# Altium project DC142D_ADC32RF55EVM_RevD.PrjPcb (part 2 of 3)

## Sheet DC142D_ADC32RF55_MUX_RevA1.SchDoc: MUXes
size 431 x 279 mm; Date: Not shown in title block; ApprovedBy: Not shown in title block; CheckedBy: Not shown in title block; Author: Not shown in title block; CompanyName: Not shown in title block; DrawnBy: CW; Engineer: Not shown in title block; Organization: Not shown in title block; Address1: Not shown in title block; Address2: Not shown in title block; Address3: Not shown in title block; Address4: Not shown in title block; DocumentNumber: 10; Revision: Use project parameter SCH_Rev; SheetNumber: 6; SheetTotal: 13; PageSetup: Record=PageOptions¦CenterHorizontal=True¦CenterVertical=True¦PrintScale=1.00¦XCorrection=1.00¦YCorrection=1.00¦PrintKind=0¦BorderSize=5000000¦LeftOffset=0¦BottomOffset=0¦Orientation=2¦PaperLength=1000¦PaperWidth=1000¦Scale=100¦PaperSource=15¦PrintQuality=600¦MediaType=1¦DitherType=10¦PaperKind=Letter¦PrintScaleMode=1
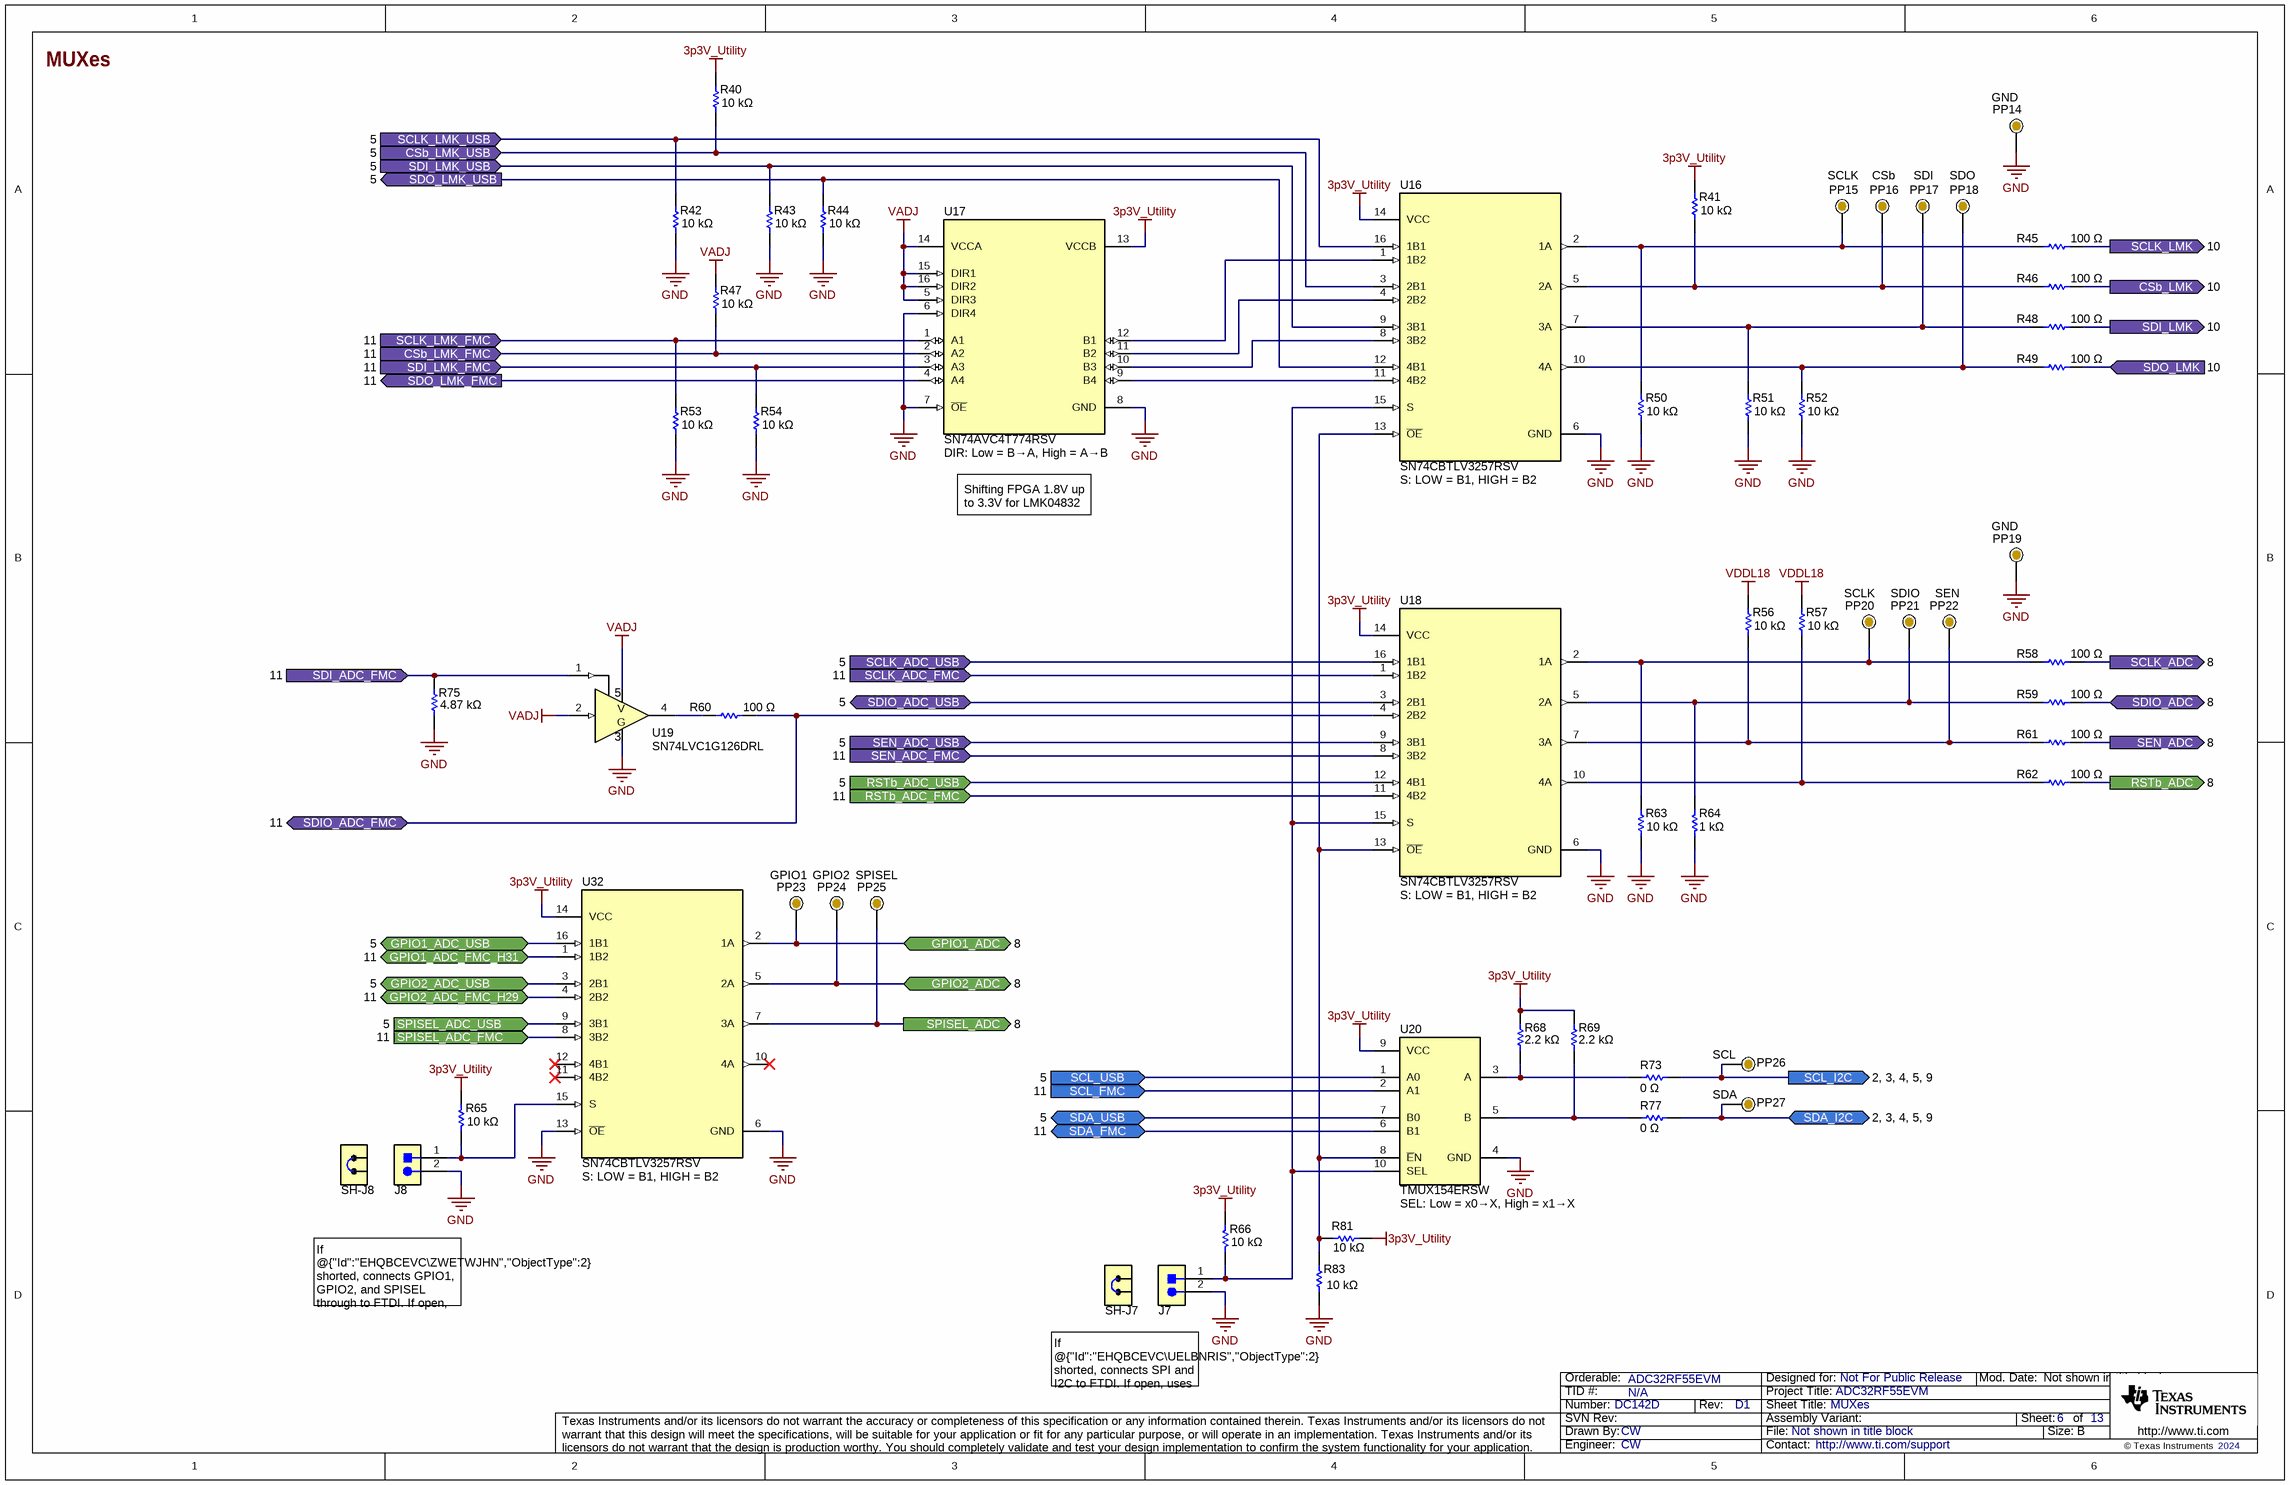
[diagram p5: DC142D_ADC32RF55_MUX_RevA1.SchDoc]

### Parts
J7  TSW-102-14-L-S  [PBC02SAAN]  (value not drawn)
J8  TSW-102-14-L-S  [PBC02SAAN]  (value not drawn)
PP14  Text1: GND  [ProbePoint_TH_40mil]  (hidden comment: Probe Point)  (no BOM)
PP15  Text1: SCLK  [ProbePoint_TH_40mil]  (hidden comment: Probe Point)  (no BOM)
PP16  Text1: CSb  [ProbePoint_TH_40mil]  (hidden comment: Probe Point)  (no BOM)
PP17  Text1: SDI  [ProbePoint_TH_40mil]  (hidden comment: Probe Point)  (no BOM)
PP18  Text1: SDO  [ProbePoint_TH_40mil]  (hidden comment: Probe Point)  (no BOM)
PP19  Text1: GND  [ProbePoint_TH_40mil]  (hidden comment: Probe Point)  (no BOM)
PP20  Text1: SCLK  [ProbePoint_TH_40mil]  (hidden comment: Probe Point)  (no BOM)
PP21  Text1: SDIO  [ProbePoint_TH_40mil]  (hidden comment: Probe Point)  (no BOM)
PP22  Text1: SEN  [ProbePoint_TH_40mil]  (hidden comment: Probe Point)  (no BOM)
PP23  Text1: GPIO1  [ProbePoint_TH_40mil]  (hidden comment: Probe Point)  (no BOM)
PP24  Text1: GPIO2  [ProbePoint_TH_40mil]  (hidden comment: Probe Point)  (no BOM)
PP25  Text1: SPISEL  [ProbePoint_TH_40mil]  (hidden comment: Probe Point)  (no BOM)
PP26  Text1: SCL  [ProbePoint_TH_40mil]  (hidden comment: Probe Point)  (no BOM)
PP27  Text1: SDA  [ProbePoint_TH_40mil]  (hidden comment: Probe Point)  (no BOM)
R40  value 10 kΩ  [0201]  (hidden comment: ERJ-1GNF1002C)
R41  value 10 kΩ  [0201]  (hidden comment: ERJ-1GNF1002C)
R42  value 10 kΩ  [0201]  (hidden comment: ERJ-1GNF1002C)
R43  value 10 kΩ  [0201]  (hidden comment: ERJ-1GNF1002C)
R44  value 10 kΩ  [0201]  (hidden comment: ERJ-1GNF1002C)
R45  value 100 Ω  [0201]  (hidden comment: ERJ-1GNF1000C)
R46  value 100 Ω  [0201]  (hidden comment: ERJ-1GNF1000C)
R47  value 10 kΩ  [0201]  (hidden comment: ERJ-1GNF1002C)
R48  value 100 Ω  [0201]  (hidden comment: ERJ-1GNF1000C)
R49  value 100 Ω  [0201]  (hidden comment: ERJ-1GNF1000C)
R50  value 10 kΩ  [0201]  (hidden comment: ERJ-1GNF1002C)
R51  value 10 kΩ  [0201]  (hidden comment: ERJ-1GNF1002C)
R52  value 10 kΩ  [0201]  (hidden comment: ERJ-1GNF1002C)
R53  value 10 kΩ  [0201]  (hidden comment: ERJ-1GNF1002C)
R54  value 10 kΩ  [0201]  (hidden comment: ERJ-1GNF1002C)
R56  value 10 kΩ  [0201]  (hidden comment: ERJ-1GNF1002C)
R57  value 10 kΩ  [0201]  (hidden comment: ERJ-1GNF1002C)
R58  value 100 Ω  [0201]  (hidden comment: ERJ-1GNF1000C)
R59  value 100 Ω  [0201]  (hidden comment: ERJ-1GNF1000C)
R60  value 100 Ω  [0201]  (hidden comment: ERJ-1GNF1000C)
R61  value 100 Ω  [0201]  (hidden comment: ERJ-1GNF1000C)
R62  value 100 Ω  [0201]  (hidden comment: ERJ-1GNF1000C)
R63  value 10 kΩ  [0201]  (hidden comment: ERJ-1GNF1002C)
R64  value 1 kΩ  [0201]  (hidden comment: ERJ-1GNF1001C)
R65  value 10 kΩ  [0201]  (hidden comment: ERJ-1GNF1002C)
R66  value 10 kΩ  [0201]  (hidden comment: ERJ-1GNF1002C)
R68  value 2.2 kΩ  [0201]  (hidden comment: ERJ-1GNF2201C)
R69  value 2.2 kΩ  [0201]  (hidden comment: ERJ-1GNF2201C)
R73  value 0 Ω  [0201]  (hidden comment: ERJ-1GN0R00C)
R75  value 4.87 kΩ  [0402L]  (hidden comment: ERJ-2RKF4871X)
R77  value 0 Ω  [0201]  (hidden comment: ERJ-1GN0R00C)
R81  value 10 kΩ  [0201]  (hidden comment: ERJ-1GNF1002C)
R83  value 10 kΩ  [0201]  (hidden comment: ERJ-1GNF1002C)
SH-J7  SPC02SYAN  [SPC02SYAN]  (value not drawn)
SH-J8  SPC02SYAN  [SPC02SYAN]  (value not drawn)
U16  SN74CBTLV3257RSV  Text1: S: LOW = B1, HIGH = B2  [RSV0016A]
U17  SN74AVC4T774RSV  Text1: DIR: Low = B→A, High = A→B  [RSV0016A]
U18  SN74CBTLV3257RSV  Text1: S: LOW = B1, HIGH = B2  [RSV0016A]
U19  SN74LVC1G126DRL  [DRL0005A]
U20  TMUX154ERSW  Text1: SEL: Low = x0→X, High = x1→X  [RSW0010A]
U32  SN74CBTLV3257RSV  Text1: S: LOW = B1, HIGH = B2  [RSV0016A]

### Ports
CSb_LMK (out, see 10), CSb_LMK_FMC (in, see 11), CSb_LMK_USB (in, see 5), GPIO1_ADC (bidir, see 8), GPIO1_ADC_FMC_H31 (bidir, see 11), GPIO1_ADC_USB (bidir, see 5), GPIO2_ADC (bidir, see 8), GPIO2_ADC_FMC_H29 (bidir, see 11), GPIO2_ADC_USB (bidir, see 5), RSTb_ADC (out, see 8), RSTb_ADC_FMC (in, see 11), RSTb_ADC_USB (in, see 5), SCL_FMC (in, see 11), SCL_I2C (out, see 2, 3, 4, 5, 9), SCL_USB (in, see 5), SCLK_ADC (out, see 8), SCLK_ADC_FMC (in, see 11), SCLK_ADC_USB (in, see 5), SCLK_LMK (out, see 10), SCLK_LMK_FMC (in, see 11), SCLK_LMK_USB (in, see 5), SDA_FMC (bidir, see 11), SDA_I2C (bidir, see 2, 3, 4, 5, 9), SDA_USB (bidir, see 5), SDI_ADC_FMC (in, see 11), SDI_LMK (out, see 10), SDI_LMK_FMC (in, see 11), SDI_LMK_USB (in, see 5), SDIO_ADC (bidir, see 8), SDIO_ADC_FMC (bidir, see 11), SDIO_ADC_USB (bidir, see 5), SDO_LMK (in, see 10), SDO_LMK_FMC (out, see 11), SDO_LMK_USB (out, see 5), SEN_ADC (out, see 8), SEN_ADC_FMC (in, see 11), SEN_ADC_USB (in, see 5), SPISEL_ADC (out, see 8), SPISEL_ADC_FMC (in, see 11), SPISEL_ADC_USB (in, see 5)

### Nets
3p3V_Utility: R40.1 R41.1 R65.2 R66.2 R68.2 R69.2 R81.1 U16.14(VCC) U17.13(VCCB) U18.14(VCC) U20.9(VCC) U32.14(VCC)
GND: J7.2 J8.2 PP14.1 PP19.1 R42.2 R43.2 R44.2 R50.2 R51.2 R52.2 R53.2 R54.2 R63.2 R64.2 R75.2 R83.1 U16.6(GND) U17.6(DIR4) U17.7(~{OE}) U17.8(GND) U18.6(GND) U19.3(GND) U20.4(GND) U32.6(GND) U32.13(~{OE})
VADJ: R47.1 U17.5(DIR3) U17.14(VCCA) U17.15(DIR1) U17.16(DIR2) U19.2(A) U19.5(VCC)
VDDL18: R56.1 R57.1
CSb_LMK: R46.2 ; port CSb_LMK
CSb_LMK_FMC: R47.2 U17.2(A2) ; port CSb_LMK_FMC
CSb_LMK_USB: R40.2 U16.3(2B1) ; port CSb_LMK_USB
GPIO1_ADC: PP23.1 U32.2(1A) ; port GPIO1_ADC
GPIO1_ADC_FMC_H31: U32.1(1B2) ; port GPIO1_ADC_FMC_H31
GPIO1_ADC_USB: U32.16(1B1) ; port GPIO1_ADC_USB
GPIO2_ADC: PP24.1 U32.5(2A) ; port GPIO2_ADC
GPIO2_ADC_FMC_H29: U32.4(2B2) ; port GPIO2_ADC_FMC_H29
GPIO2_ADC_USB: U32.3(2B1) ; port GPIO2_ADC_USB
RSTb_ADC: R62.2 ; port RSTb_ADC
RSTb_ADC_FMC: U18.11(4B2) ; port RSTb_ADC_FMC
RSTb_ADC_USB: U18.12(4B1) ; port RSTb_ADC_USB
SCL_FMC: U20.2(A1) ; port SCL_FMC
SCL_I2C: PP26.1 R73.2 ; port SCL_I2C
SCL_USB: U20.1(A0) ; port SCL_USB
SCLK_ADC: R58.2 ; port SCLK_ADC
SCLK_ADC_FMC: U18.1(1B2) ; port SCLK_ADC_FMC
SCLK_ADC_USB: U18.16(1B1) ; port SCLK_ADC_USB
SCLK_LMK: R45.2 ; port SCLK_LMK
SCLK_LMK_FMC: R53.1 U17.1(A1) ; port SCLK_LMK_FMC
SCLK_LMK_USB: R42.1 U16.16(1B1) ; port SCLK_LMK_USB
SDA_FMC: U20.6(B1) ; port SDA_FMC
SDA_I2C: PP27.1 R77.2 ; port SDA_I2C
SDA_USB: U20.7(B0) ; port SDA_USB
SDI_ADC_FMC: R75.1 U19.1(~{OE}) ; port SDI_ADC_FMC
SDI_LMK: R48.2 ; port SDI_LMK
SDI_LMK_FMC: R54.1 U17.3(A3) ; port SDI_LMK_FMC
SDI_LMK_USB: R43.1 U16.9(3B1) ; port SDI_LMK_USB
SDIO_ADC: R59.2 ; port SDIO_ADC
SDIO_ADC_FMC: R60.2 U18.4(2B2) ; port SDIO_ADC_FMC
SDIO_ADC_USB: U18.3(2B1) ; port SDIO_ADC_USB
SDO_LMK: R49.2 ; port SDO_LMK
SDO_LMK_FMC: U17.4(A4) ; port SDO_LMK_FMC
SDO_LMK_USB: R44.1 U16.12(4B1) ; port SDO_LMK_USB
SEN_ADC: R61.2 ; port SEN_ADC
SEN_ADC_FMC: U18.8(3B2) ; port SEN_ADC_FMC
SEN_ADC_USB: U18.9(3B1) ; port SEN_ADC_USB
SPISEL_ADC: PP25.1 U32.7(3A) ; port SPISEL_ADC
SPISEL_ADC_FMC: U32.8(3B2) ; port SPISEL_ADC_FMC
SPISEL_ADC_USB: U32.9(3B1) ; port SPISEL_ADC_USB
NetJ7_1: J7.1 R66.1 U16.15(S) U18.15(S) U20.10(SEL)
NetJ8_1: J8.1 R65.1 U32.15(S)
NetPP15_1: PP15.1 R45.1 R50.1 U16.2(1A)
NetPP16_1: PP16.1 R41.2 R46.1 U16.5(2A)
NetPP17_1: PP17.1 R48.1 R51.1 U16.7(3A)
NetPP18_1: PP18.1 R49.1 R52.1 U16.10(4A)
NetPP20_1: PP20.1 R58.1 R63.1 U18.2(1A)
NetPP21_1: PP21.1 R59.1 R64.1 U18.5(2A)
NetPP22_1: PP22.1 R56.2 R61.1 U18.7(3A)
NetR57_2: R57.2 R62.1 U18.10(4A)
NetR60_1: R60.1 U19.4(Y)
NetR68_1: R68.1 R73.1 U20.3(A)
NetR69_1: R69.1 R77.1 U20.5(B)
NetR81_2: R81.2 R83.2 U16.13(~{OE}) U18.13(~{OE}) U20.8(~{E}N)
NetU16_1: U16.1(1B2) U17.12(B1)
NetU16_4: U16.4(2B2) U17.11(B2)
NetU16_8: U16.8(3B2) U17.10(B3)
NetU16_11: U16.11(4B2) U17.9(B4)

Not connected (* = marked no-connect by the designer): U32 10(4A)* 11(4B2)* 12(4B1)*

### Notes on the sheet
- Shifting FPGA 1.8V up to 3.3V for LMK04832
- If @{"Id":"EHQBCEVC\ZWETWJHN","ObjectType":2} shorted, connects GPIO1, GPIO2, and SPISEL through to FTDI. If open, uses FPGA.
- If @{"Id":"EHQBCEVC\UELBNRIS","ObjectType":2} shorted, connects SPI and I2C to FTDI. If open, uses FPGA.

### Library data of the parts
J7 J8 = TSW-102-14-L-S: Header, 100mil, 2x1, Gold, TH; Manufacturer: Samtec; Alt Manufacturer: Sullins Connector Solutions; UniqueID: cmp00014; Pitch (mm): 2.54
PP14-PP27 = cmp00025: Probe Point that can be used in lue of a test point
R40-R44 R47 R50-R54 R56 R57 R63 R65 R66 R81 R83 = RSMD020100762: RES SMD 10K OHM 1% 1/20W 0201; Manufacturer: Panasonic Electronic Components; CompType: Resistor SMD; Power (Watts): 0.05W, 1/20W; Temperature Coefficient: ±200ppm/°C
R45 R46 R48 R49 R58-R62 = RSMD020100289: RES SMD 100 OHM 1% 1/20W 0201; Manufacturer: Panasonic Electronic Components; CompType: Resistor SMD; Power (Watts): 0.05W, 1/20W; Temperature Coefficient: ±200ppm/°C
R64 = RSMD020100143: RES SMD 1K OHM 1% 1/20W 0201; Manufacturer: Panasonic Electronic Components; CompType: Resistor SMD; Power (Watts): 0.05W, 1/20W; Temperature Coefficient: ±200ppm/°C
R68 R69 = RSMD020100606: RES SMD 2.2K OHM 1% 1/20W 0201; Manufacturer: Panasonic Electronic Components; CompType: Resistor SMD; Power (Watts): 0.05W, 1/20W; Temperature Coefficient: ±200ppm/°C
R73 R77 = RSMD020101699: RES SMD 0 OHM JUMPER 1/20W 0201; Manufacturer: Panasonic Electronic Components; CompType: Resistor SMD; Power (Watts): 0.05W, 1/20W
R75 = RSMD040202616: RES SMD 4.87K OHM 1% 1/10W 0402; Manufacturer: Panasonic Electronic Components; CompType: Resistor SMD; Power (Watts): 0.1W, 1/10W; Temperature Coefficient: ±100ppm/°C; SizeX_mm: 1; SizeY_mm: 0.5; SizeZ_mm: 0.4
SH-J7 SH-J8 = cmp00093: 2 (1 x 2) Position Shunt Connector Black Closed Top 0.100" (2.54mm) Gold; Manufacturer: Sullins; Value: 1x2; Note: You can "mate" this to a header by matching the designator.  i.e. use SH-J3 for header J3; Pitch (mm): 2.54
U16 U18 U32 = SN74CBTLV3257RSV: Low-Voltage 4-Bit 1-of-2 FET Multiplexer/Demultiplexe; PartNumber: SN74CBTLV3257RSVR; Manufacturer: Texas Instruments; UniqueID: cmp00269; CompType: MUX
U17 = cmp00171: Translation - Voltage Levels 4-bit dual-supply bus transceiver with 3-state outputs and independent direction control inputs; Manufacturer: Texas Instruments; Alt PartNumber: SN74AXC4T774RSV; CompType: Level Shifter
U19 = SN74LVC1G126DRL: Single Bus Buffer Gate With 3-State Outputs. Active high enable.; Manufacturer: Texas Instruments
U20 = cmp00300: ESD-Protected, Low Capacitance, 2-Channel, 2:1 Switch, With Powered-off Protection; PartNumber: TMUX154ERSWR; Manufacturer: Texas Instruments; CompType: MUX

## Sheet DC142D_ADC32RF55_ADC_Input_RevA1.SchDoc: ADC EVM RF Input
size 431 x 279 mm; Date: Not shown in title block; ApprovedBy: Not shown in title block; CheckedBy: Not shown in title block; Author: Not shown in title block; CompanyName: Not shown in title block; DrawnBy: CW; Engineer: Not shown in title block; Organization: Not shown in title block; Address1: Not shown in title block; Address2: Not shown in title block; Address3: Not shown in title block; Address4: Not shown in title block; DocumentNumber: 2; Revision: Use project parameter SCH_Rev; SheetNumber: 7; SheetTotal: 13; PageSetup: Record=PageOptions¦CenterHorizontal=True¦CenterVertical=True¦PrintScale=1.00¦XCorrection=1.00¦YCorrection=1.00¦PrintKind=0¦BorderSize=5000000¦LeftOffset=0¦BottomOffset=0¦Orientation=2¦PaperLength=1000¦PaperWidth=1000¦Scale=100¦PaperSource=15¦PrintQuality=600¦MediaType=1¦DitherType=10¦PaperKind=Letter¦PrintScaleMode=1
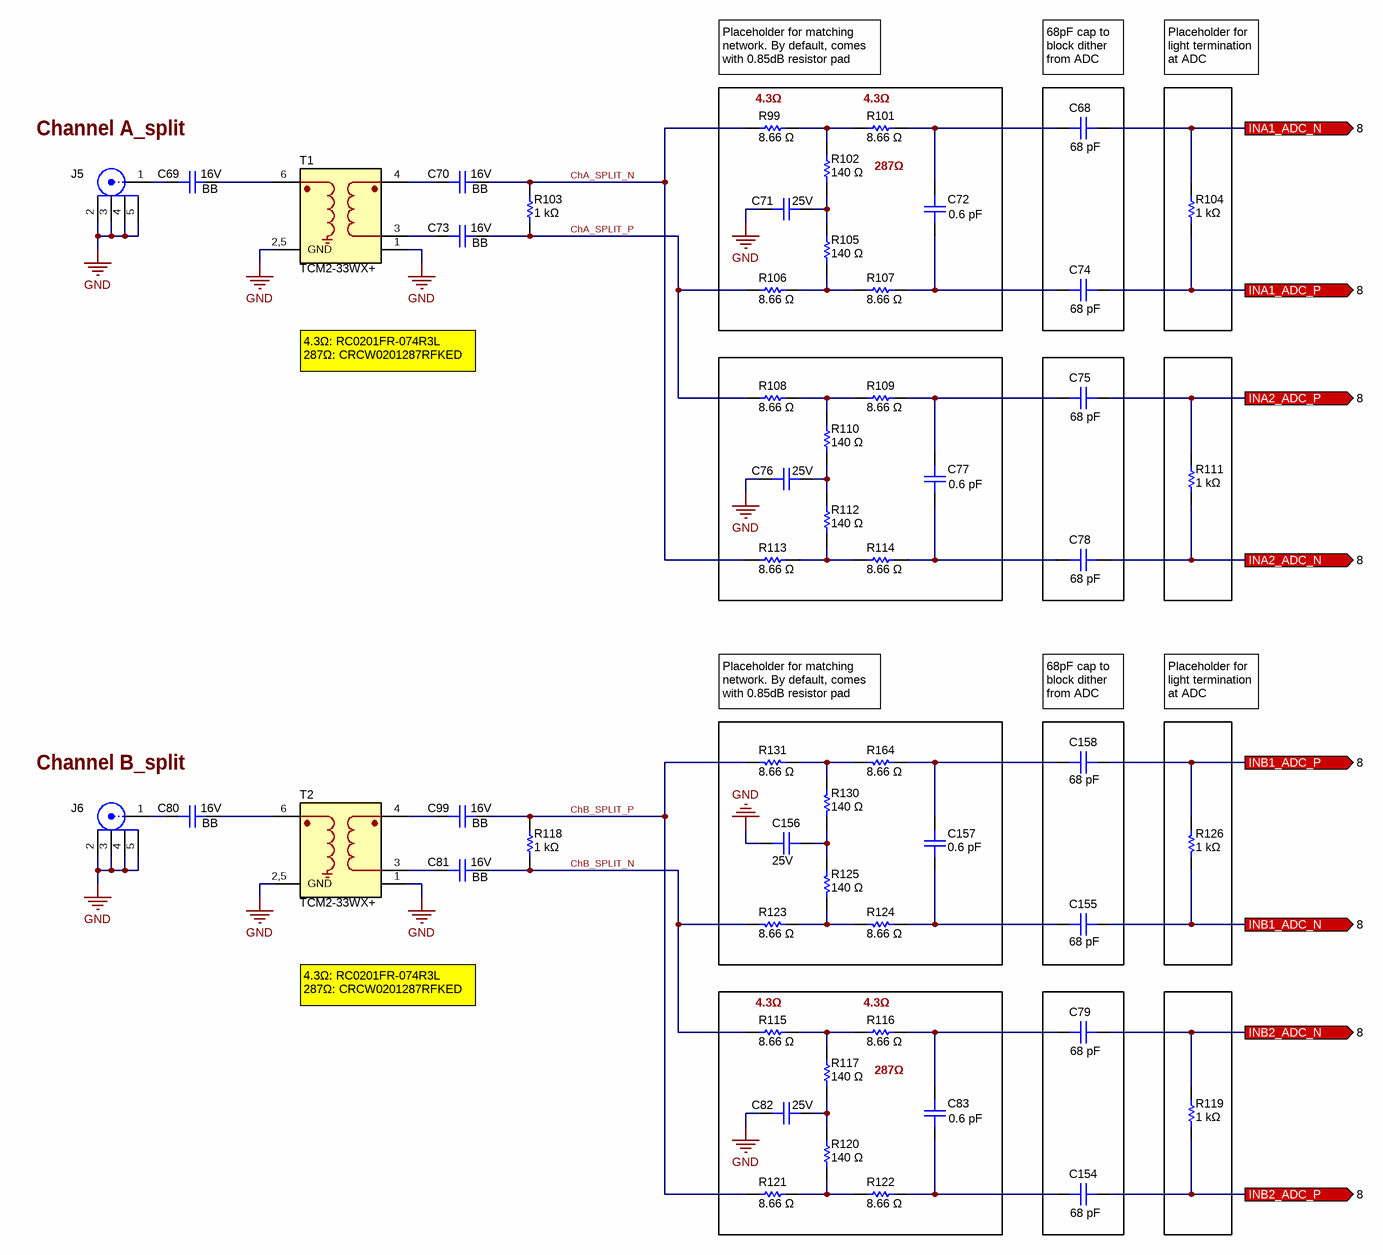
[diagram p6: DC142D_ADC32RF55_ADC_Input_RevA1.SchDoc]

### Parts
C68  value 68 pF  [0201_cap]  (hidden comment: GRM0335C1E680FA01D)
C69  Voltage - Rated: 16V  Text: BB  [0201_cap]  (hidden comment: 0201BB104KW160)
C70  Voltage - Rated: 16V  Text: BB  [0201_cap]  (hidden comment: 0201BB104KW160)
C71  Voltage - Rated: 25V  [0201_cap]  (hidden comment: C0603X5R1E104K030BB)
C72  value 0.6 pF  [0201_cap]  (hidden comment: GJM0335C1HR60WB01D)
C73  Voltage - Rated: 16V  Text: BB  [0201_cap]  (hidden comment: 0201BB104KW160)
C74  value 68 pF  [0201_cap]  (hidden comment: GRM0335C1E680FA01D)
C75  value 68 pF  [0201_cap]  (hidden comment: GRM0335C1E680FA01D)
C76  Voltage - Rated: 25V  [0201_cap]  (hidden comment: C0603X5R1E104K030BB)
C77  value 0.6 pF  [0201_cap]  (hidden comment: GJM0335C1HR60WB01D)
C78  value 68 pF  [0201_cap]  (hidden comment: GRM0335C1E680FA01D)
C79  value 68 pF  [0201_cap]  (hidden comment: GRM0335C1E680FA01D)
C80  Voltage - Rated: 16V  Text: BB  [0201_cap]  (hidden comment: 0201BB104KW160)
C81  Voltage - Rated: 16V  Text: BB  [0201_cap]  (hidden comment: 0201BB104KW160)
C82  Voltage - Rated: 25V  [0201_cap]  (hidden comment: C0603X5R1E104K030BB)
C83  value 0.6 pF  [0201_cap]  (hidden comment: GJM0335C1HR60WB01D)
C99  Voltage - Rated: 16V  Text: BB  [0201_cap]  (hidden comment: 0201BB104KW160)
C154  value 68 pF  [0201_cap]  (hidden comment: GRM0335C1E680FA01D)
C155  value 68 pF  [0201_cap]  (hidden comment: GRM0335C1E680FA01D)
C156  Voltage - Rated: 25V  [0201_cap]  (hidden comment: C0603X5R1E104K030BB)
C157  value 0.6 pF  [0201_cap]  (hidden comment: GJM0335C1HR60WB01D)
C158  value 68 pF  [0201_cap]  (hidden comment: GRM0335C1E680FA01D)
J5  SASF546-P26-X1  [FP-132134-15_CONN_SMA_JACK-MFG]  (value not drawn)
J6  SASF546-P26-X1  [FP-132134-15_CONN_SMA_JACK-MFG]  (value not drawn)
R99  value 8.66 Ω  [0201]  (hidden comment: RC0201FR-078R66L)
R101  value 8.66 Ω  [0201]  (hidden comment: RC0201FR-078R66L)
R102  value 140 Ω  [0201]  (hidden comment: ERJ-1GNF1400C)
R103  value 1 kΩ  [0201]  (hidden comment: ERJ-1GNF1001C)
R104  value 1 kΩ  [0201]  (hidden comment: ERJ-1GNF1001C)
R105  value 140 Ω  [0201]  (hidden comment: ERJ-1GNF1400C)
R106  value 8.66 Ω  [0201]  (hidden comment: RC0201FR-078R66L)
R107  value 8.66 Ω  [0201]  (hidden comment: RC0201FR-078R66L)
R108  value 8.66 Ω  [0201]  (hidden comment: RC0201FR-078R66L)
R109  value 8.66 Ω  [0201]  (hidden comment: RC0201FR-078R66L)
R110  value 140 Ω  [0201]  (hidden comment: ERJ-1GNF1400C)
R111  value 1 kΩ  [0201]  (hidden comment: ERJ-1GNF1001C)
R112  value 140 Ω  [0201]  (hidden comment: ERJ-1GNF1400C)
R113  value 8.66 Ω  [0201]  (hidden comment: RC0201FR-078R66L)
R114  value 8.66 Ω  [0201]  (hidden comment: RC0201FR-078R66L)
R115  value 8.66 Ω  [0201]  (hidden comment: RC0201FR-078R66L)
R116  value 8.66 Ω  [0201]  (hidden comment: RC0201FR-078R66L)
R117  value 140 Ω  [0201]  (hidden comment: ERJ-1GNF1400C)
R118  value 1 kΩ  [0201]  (hidden comment: ERJ-1GNF1001C)
R119  value 1 kΩ  [0201]  (hidden comment: ERJ-1GNF1001C)
R120  value 140 Ω  [0201]  (hidden comment: ERJ-1GNF1400C)
R121  value 8.66 Ω  [0201]  (hidden comment: RC0201FR-078R66L)
R122  value 8.66 Ω  [0201]  (hidden comment: RC0201FR-078R66L)
R123  value 8.66 Ω  [0201]  (hidden comment: RC0201FR-078R66L)
R124  value 8.66 Ω  [0201]  (hidden comment: RC0201FR-078R66L)
R125  value 140 Ω  [0201]  (hidden comment: ERJ-1GNF1400C)
R126  value 1 kΩ  [0201]  (hidden comment: ERJ-1GNF1001C)
R130  value 140 Ω  [0201]  (hidden comment: ERJ-1GNF1400C)
R131  value 8.66 Ω  [0201]  (hidden comment: RC0201FR-078R66L)
R164  value 8.66 Ω  [0201]  (hidden comment: RC0201FR-078R66L)
T1  TCM2-33WX+  [DB1627 - Vias 1,2,5]
T2  TCM2-33WX+  [DB1627 - Vias 1,2,5]

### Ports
INA1_ADC_N (out, see 8), INA1_ADC_P (out, see 8), INA2_ADC_N (out, see 8), INA2_ADC_P (out, see 8), INB1_ADC_N (out, see 8), INB1_ADC_P (out, see 8), INB2_ADC_N (out, see 8), INB2_ADC_P (out, see 8)

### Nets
GND: C71.1 C76.1 C82.1 C156.1 J5.2 J5.3 J5.4 J5.5 J6.2 J6.3 J6.4 J6.5 T1.1 T1.2,5(GND) T2.1 T2.2,5(GND)
ChA_SPLIT_N: C70.2 R99.1 R103.2 R113.1
ChA_SPLIT_P: C73.2 R103.1 R106.1 R108.1
ChB_SPLIT_N: C81.2 R115.1 R118.1 R123.1
ChB_SPLIT_P: C99.2 R118.2 R121.1 R131.1
INA1_ADC_N: C68.2 R104.2 ; port INA1_ADC_N
INA1_ADC_P: C74.2 R104.1 ; port INA1_ADC_P
INA2_ADC_N: C78.2 R111.1 ; port INA2_ADC_N
INA2_ADC_P: C75.2 R111.2 ; port INA2_ADC_P
INB1_ADC_N: C155.2 R126.2 ; port INB1_ADC_N
INB1_ADC_P: C158.2 R126.1 ; port INB1_ADC_P
INB2_ADC_N: C79.2 R119.2 ; port INB2_ADC_N
INB2_ADC_P: C154.2 R119.1 ; port INB2_ADC_P
NetC68_1: C68.1 C72.2 R101.2
NetC69_1: C69.1 J5.1
NetC69_2: C69.2 T1.6(Primary_Dot)
NetC70_1: C70.1 T1.4(Secondary_Dot)
NetC71_2: C71.2 R102.1 R105.2
NetC72_1: C72.1 C74.1 R107.2
NetC73_1: C73.1 T1.3
NetC75_1: C75.1 C77.2 R109.2
NetC76_2: C76.2 R110.1 R112.2
NetC77_1: C77.1 C78.1 R114.2
NetC79_1: C79.1 C83.2 R116.2
NetC80_1: C80.1 J6.1
NetC80_2: C80.2 T2.6(Primary_Dot)
NetC81_1: C81.1 T2.3
NetC82_2: C82.2 R117.1 R120.2
NetC83_1: C83.1 C154.1 R122.2
NetC99_1: C99.1 T2.4(Secondary_Dot)
NetC155_1: C155.1 C157.2 R124.2
NetC156_2: C156.2 R125.1 R130.2
NetC157_1: C157.1 C158.1 R164.2
NetR99_2: R99.2 R101.1 R102.2
NetR105_1: R105.1 R106.2 R107.1
NetR108_2: R108.2 R109.1 R110.2
NetR112_1: R112.1 R113.2 R114.1
NetR115_2: R115.2 R116.1 R117.2
NetR120_1: R120.1 R121.2 R122.1
NetR123_2: R123.2 R124.1 R125.2
NetR130_1: R130.1 R131.2 R164.1

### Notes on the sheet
- Placeholder for matching network. By default, comes with 0.85dB resistor pad
- 68pF cap to block dither from ADC
- Placeholder for light termination at ADC
- Channel A_split
- (near R99) 4.3Ω
- (near R101) 4.3Ω
- 287Ω
- 4.3Ω: RC0201FR-074R3L
  287Ω: CRCW0201287RFKED
- Channel B_split
- (near R115) 4.3Ω
- (near R116) 4.3Ω

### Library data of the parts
C68 C74 C75 C78 C79 C154 C155 C158 = capcc08427: CAP CER 68PF 25V C0G/NP0 0201; Manufacturer: Murata Electronics; CompType: Capacitor Ceramic; Tolerance: ±1%; Temperature Coefficient: C0G, NP0; SizeX_mm: 0.6; SizeY_mm: 0.3; SizeZ_mm: 0.33
C69 C70 C73 C80 C81 C99 = 0201RFCaps0693: Broadband Capacitors; Manufacturer: Passive Plus; Alt PartNumber: GRM033C71C104ME14D; Alt Manufacturer: Murata Electronics; Value: 0.1 uF; SizeZ_mm: 0.33; SizeY_mm: 0.3; CompType: Capactior RF; SizeX_mm: 0.58; Tolerance: ±10%; Temperature Coefficient: C0G, NP0
C71 C76 C82 C156 = capcc01294: CAP CER 0.1UF 25V X5R 0201; Manufacturer: TDK Corporation; SizeZ_mm: 0.33; SizeY_mm: 0.3; CompType: Capacitor Ceramic; SizeX_mm: 0.6; Tolerance: ±10%
C72 C77 C83 C157 = capcc06867: CAP CER 0.6PF 50V C0G/NP0 0201; Manufacturer: Murata Electronics; CompType: Capacitor Ceramic; Tolerance: ±0.05pF; Temperature Coefficient: C0G, NP0; SizeX_mm: 0.6; SizeY_mm: 0.3; SizeZ_mm: 0.33
J5 J6 = 132134-15: SMA Connector Jack, Female Socket 50Ohm Surface Mount, Through Hole Solder; Manufacturer: Amphenol RF; CompType: RF Connector; UniqueID: cmp00028; Text1: Silk
R99 R101 R106-R109 R113-R116 R121-R124 R131 R164 = RSMD020101700: Thick Film Resistors - SMD 8.66Ohms 1/20W 0201 1%; Manufacturer: Yageo; CompType: Resistor SMD; Power (Watts): 0.05W, 1/20W; Temperature Coefficient: - 100 PPM / C, + 350 PPM / C
R102 R105 R110 R112 R117 R120 R125 R130 = RSMD020100157: RES SMD 140 OHM 1% 1/20W 0201; Manufacturer: Panasonic Electronic Components; CompType: Resistor SMD; Power (Watts): 0.05W, 1/20W; Temperature Coefficient: ±200ppm/°C
R103 R104 R111 R118 R119 R126 = RSMD020100143: as R64 on sheet DC142D_ADC32RF55_MUX_RevA1
T1 T2 = TCM2-33WX+: 1:2 CORE & WIRE Transformer, 10 to 3000 MHz, 50Ω; Manufacturer: Mini-Circuits; UniqueID: cmp00349; CompType: Balun

## Sheet DC142D_ADC32RF55_ADC_Dig_RevA1.SchDoc: ADC Input, SERDES and Digital Pins
size 431 x 279 mm; Date: Not shown in title block; ApprovedBy: Not shown in title block; CheckedBy: Not shown in title block; Author: Not shown in title block; CompanyName: Not shown in title block; DrawnBy: CW; Engineer: Not shown in title block; Organization: Not shown in title block; Address1: Not shown in title block; Address2: Not shown in title block; Address3: Not shown in title block; Address4: Not shown in title block; DocumentNumber: 3; Revision: Use project parameter SCH_Rev; SheetNumber: 8; SheetTotal: 13; PageSetup: Record=PageOptions¦CenterHorizontal=True¦CenterVertical=True¦PrintScale=1.00¦XCorrection=1.00¦YCorrection=1.00¦PrintKind=0¦BorderSize=5000000¦LeftOffset=0¦BottomOffset=0¦Orientation=2¦PaperLength=1000¦PaperWidth=1000¦Scale=100¦PaperSource=15¦PrintQuality=600¦MediaType=1¦DitherType=10¦PaperKind=Letter¦PrintScaleMode=1
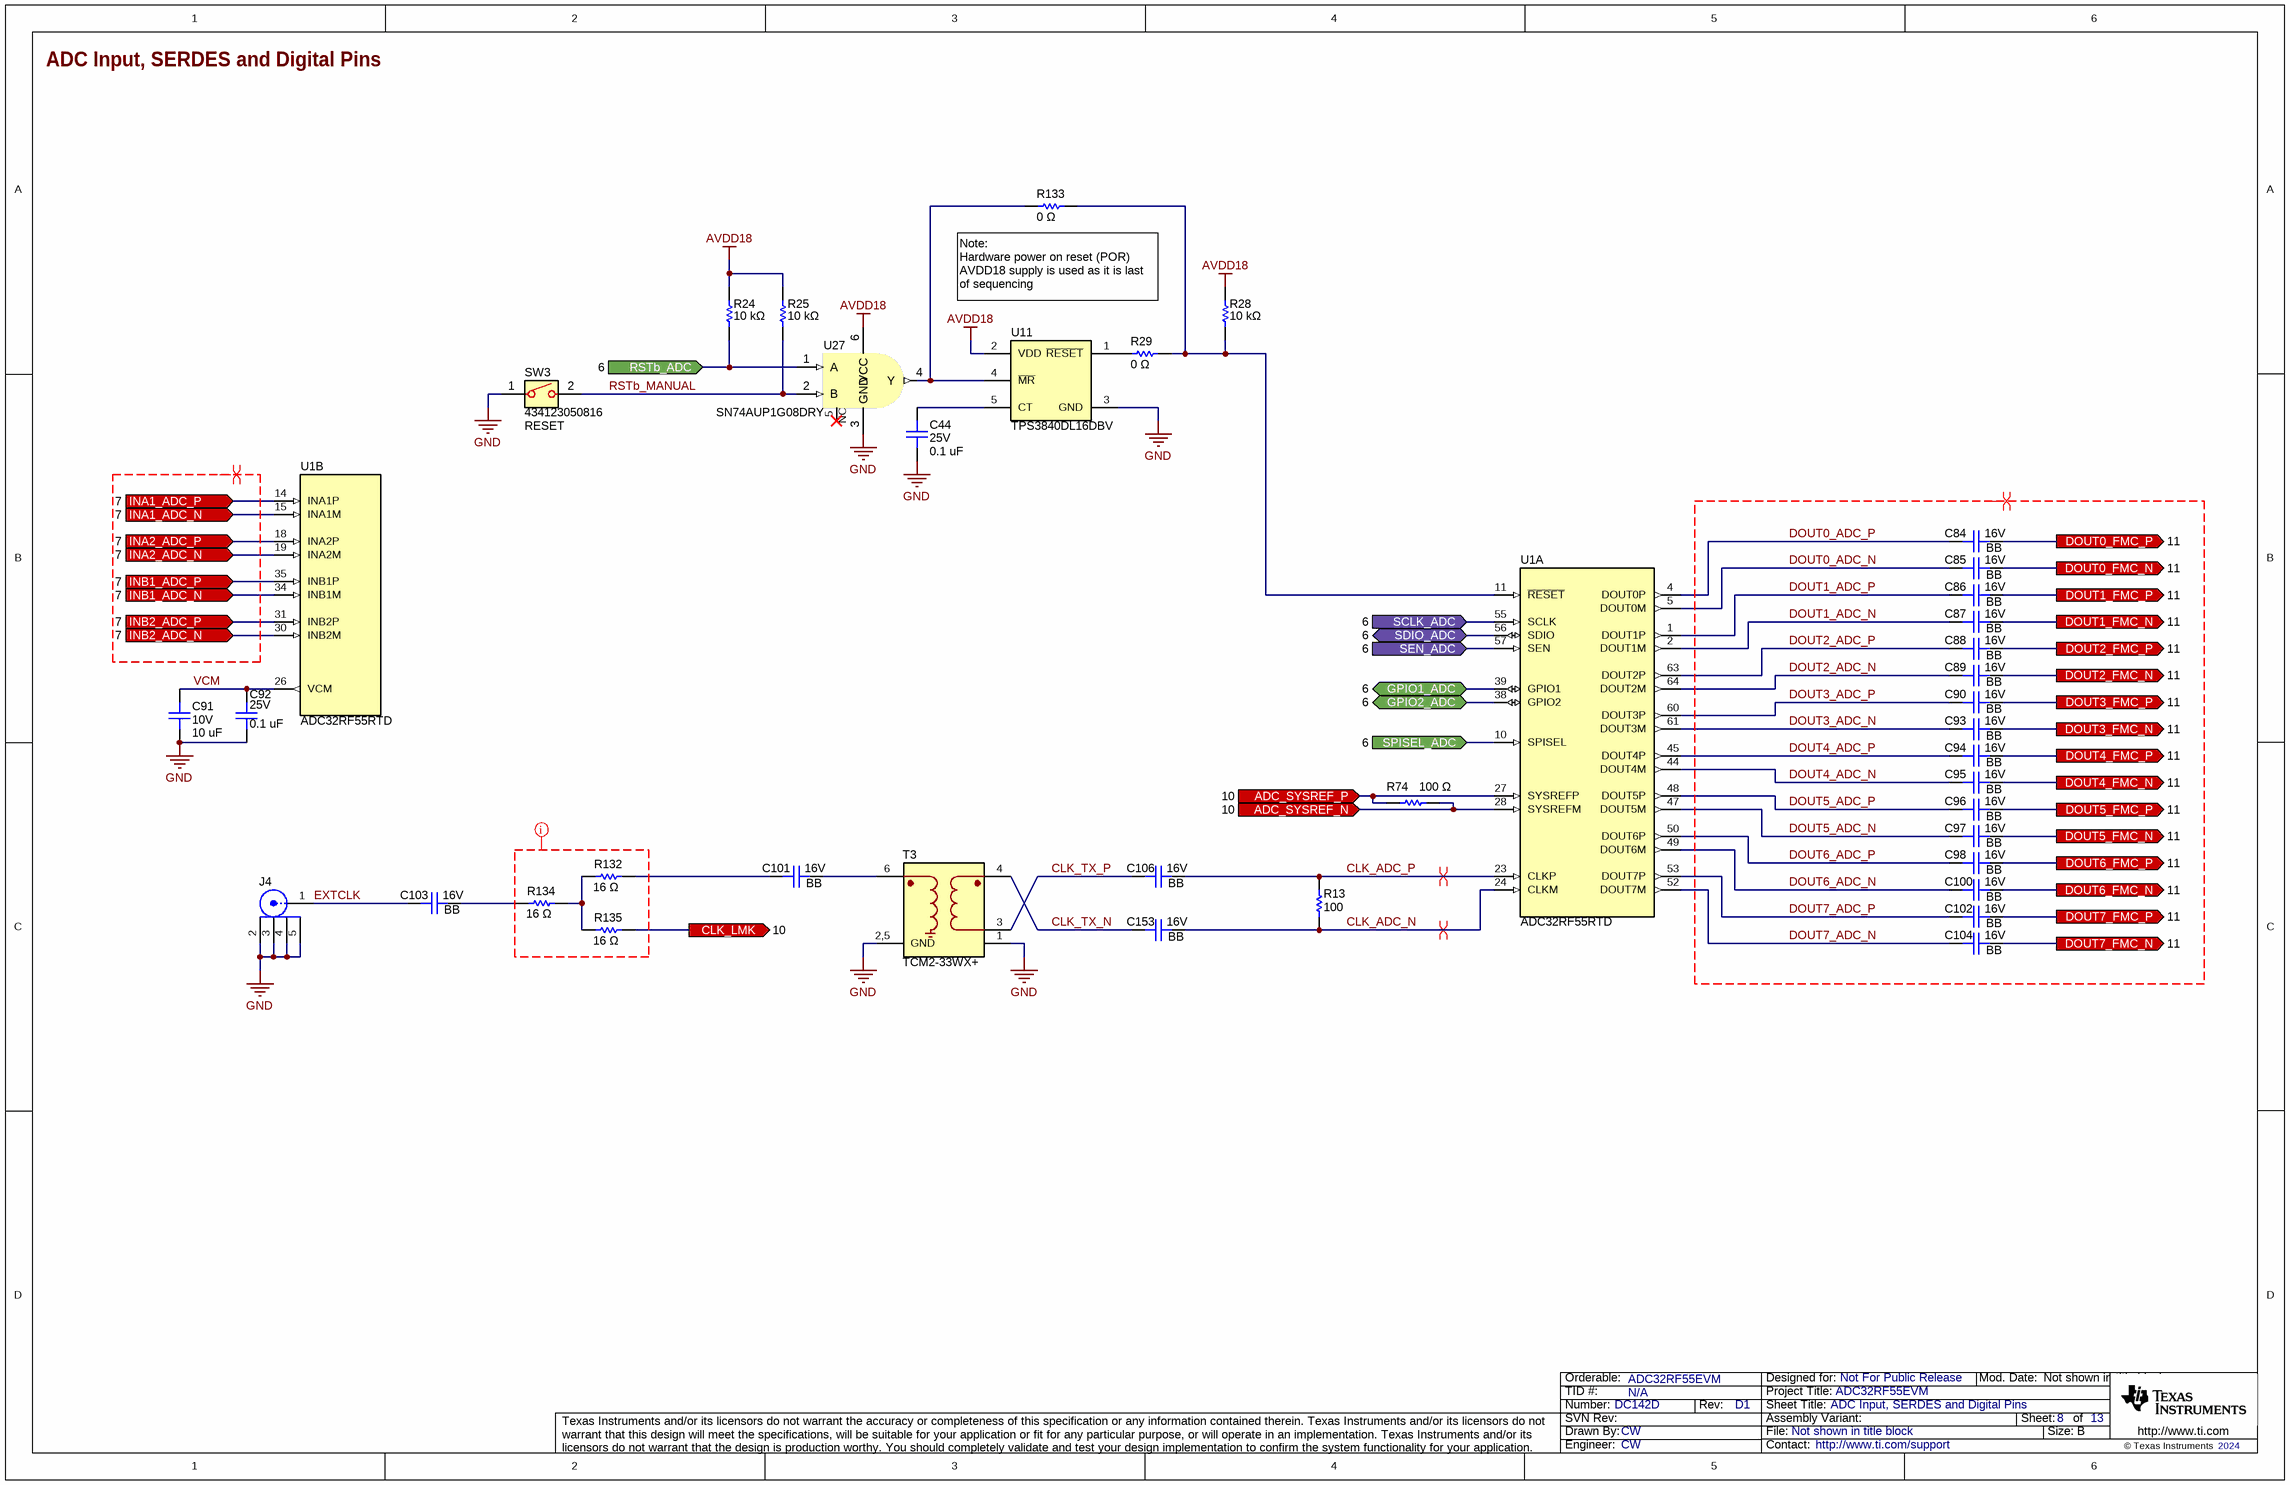
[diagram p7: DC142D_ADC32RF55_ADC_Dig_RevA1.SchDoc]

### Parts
C44  value 0.1 uF  Voltage - Rated: 25V  [0201_cap]  (hidden comment: C0603X5R1E104K030BB)
C84  Voltage - Rated: 16V  Text: BB  [0201_cap]  (hidden comment: 0201BB104KW160)
C85  Voltage - Rated: 16V  Text: BB  [0201_cap]  (hidden comment: 0201BB104KW160)
C86  Voltage - Rated: 16V  Text: BB  [0201_cap]  (hidden comment: 0201BB104KW160)
C87  Voltage - Rated: 16V  Text: BB  [0201_cap]  (hidden comment: 0201BB104KW160)
C88  Voltage - Rated: 16V  Text: BB  [0201_cap]  (hidden comment: 0201BB104KW160)
C89  Voltage - Rated: 16V  Text: BB  [0201_cap]  (hidden comment: 0201BB104KW160)
C90  Voltage - Rated: 16V  Text: BB  [0201_cap]  (hidden comment: 0201BB104KW160)
C91  value 10 uF  Voltage - Rated: 10V  [0402L_cap]  (hidden comment: 0402ZD106MAT2A)
C92  value 0.1 uF  Voltage - Rated: 25V  [0201_cap]  (hidden comment: C0603X5R1E104K030BB)
C93  Voltage - Rated: 16V  Text: BB  [0201_cap]  (hidden comment: 0201BB104KW160)
C94  Voltage - Rated: 16V  Text: BB  [0201_cap]  (hidden comment: 0201BB104KW160)
C95  Voltage - Rated: 16V  Text: BB  [0201_cap]  (hidden comment: 0201BB104KW160)
C96  Voltage - Rated: 16V  Text: BB  [0201_cap]  (hidden comment: 0201BB104KW160)
C97  Voltage - Rated: 16V  Text: BB  [0201_cap]  (hidden comment: 0201BB104KW160)
C98  Voltage - Rated: 16V  Text: BB  [0201_cap]  (hidden comment: 0201BB104KW160)
C100  Voltage - Rated: 16V  Text: BB  [0201_cap]  (hidden comment: 0201BB104KW160)
C101  Voltage - Rated: 16V  Text: BB  [0201_cap]  (hidden comment: 0201BB104KW160)
C102  Voltage - Rated: 16V  Text: BB  [0201_cap]  (hidden comment: 0201BB104KW160)
C103  Voltage - Rated: 16V  Text: BB  [0201_cap]  (hidden comment: 0201BB104KW160)
C104  Voltage - Rated: 16V  Text: BB  [0201_cap]  (hidden comment: 0201BB104KW160)
C106  Voltage - Rated: 16V  Text: BB  [0201_cap]  (hidden comment: 0201BB104KW160)
C153  Voltage - Rated: 16V  Text: BB  [0201_cap]  (hidden comment: 0201BB104KW160)
J4  SASF546-P26-X1  [FP-132134-15_CONN_SMA_JACK-MFG]  (value not drawn)
R13  ValueDisplayed: 100  [0201L]  (hidden comment: RC0201FS-7D100RL)
R24  value 10 kΩ  [0201]  (hidden comment: ERJ-1GNF1002C)
R25  value 10 kΩ  [0201]  (hidden comment: ERJ-1GNF1002C)
R28  value 10 kΩ  [0201]  (hidden comment: ERJ-1GNF1002C)
R29  value 0 Ω  [0201]  (hidden comment: ERJ-1GN0R00C)
R74  value 100 Ω  [0201]  (hidden comment: ERJ-1GNF1000C)
R132  value 16 Ω  [0201]  (hidden comment: ERJ-1GNF16R0C)
R133  value 0 Ω  [0201]  (hidden comment: ERJ-1GN0R00C)
R134  value 16 Ω  [0201]  (hidden comment: ERJ-1GNF16R0C)
R135  value 16 Ω  [0201]  (hidden comment: ERJ-1GNF16R0C)
SW3  434123050816  Text1: RESET  [434123050816]
T3  TCM2-33WX+  [DB1627 - Vias 1,2,5]
U1  ADC32RF55RTD  [RTD0064L]  (parts A,B of 3)
U11  TPS3840DL16DBV  [DBV0005A]
U27  SN74AUP1G08DRY  [DRY0006A]

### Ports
ADC_SYSREF_N (in, see 10), ADC_SYSREF_P (in, see 10), CLK_LMK (out, see 10), DOUT0_FMC_N (out, see 11), DOUT0_FMC_P (out, see 11), DOUT1_FMC_N (out, see 11), DOUT1_FMC_P (out, see 11), DOUT2_FMC_N (out, see 11), DOUT2_FMC_P (out, see 11), DOUT3_FMC_N (out, see 11), DOUT3_FMC_P (out, see 11), DOUT4_FMC_N (out, see 11), DOUT4_FMC_P (out, see 11), DOUT5_FMC_N (out, see 11), DOUT5_FMC_P (out, see 11), DOUT6_FMC_N (out, see 11), DOUT6_FMC_P (out, see 11), DOUT7_FMC_N (out, see 11), DOUT7_FMC_P (out, see 11), GPIO1_ADC (bidir, see 6), GPIO2_ADC (bidir, see 6), INA1_ADC_N (in, see 7), INA1_ADC_P (in, see 7), INA2_ADC_N (in, see 7), INA2_ADC_P (in, see 7), INB1_ADC_N (in, see 7), INB1_ADC_P (in, see 7), INB2_ADC_N (in, see 7), INB2_ADC_P (in, see 7), RSTb_ADC (in, see 6), SCLK_ADC (in, see 6), SDIO_ADC (bidir, see 6), SEN_ADC (in, see 6), SPISEL_ADC (in, see 6)

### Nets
AVDD18: R24.1 R25.1 R28.1 U11.2(VDD) U27.6(VCC)
GND: C44.1 C91.1 C92.1 J4.2 J4.3 J4.4 J4.5 SW3.1 T3.1 T3.2,5(GND) U11.3(GND) U27.3(GND)
ADC_SYSREF_N: R74.2 U1.28(SYSREFM) ; port ADC_SYSREF_N
ADC_SYSREF_P: R74.1 U1.27(SYSREFP) ; port ADC_SYSREF_P
CLK_ADC_N: C153.2 R13.2 U1.24(CLKM)
CLK_ADC_P: C106.2 R13.1 U1.23(CLKP)
CLK_LMK: R135.2 ; port CLK_LMK
CLK_TX_N: C153.1 T3.4(Secondary_Dot)
CLK_TX_P: C106.1 T3.3
DOUT0_ADC_N: C85.1 U1.5(DOUT0M)
DOUT0_ADC_P: C84.1 U1.4(DOUT0P)
DOUT0_FMC_N: C85.2 ; port DOUT0_FMC_N
DOUT0_FMC_P: C84.2 ; port DOUT0_FMC_P
DOUT1_ADC_N: C87.1 U1.2(DOUT1M)
DOUT1_ADC_P: C86.1 U1.1(DOUT1P)
DOUT1_FMC_N: C87.2 ; port DOUT1_FMC_N
DOUT1_FMC_P: C86.2 ; port DOUT1_FMC_P
DOUT2_ADC_N: C89.1 U1.64(DOUT2M)
DOUT2_ADC_P: C88.1 U1.63(DOUT2P)
DOUT2_FMC_N: C89.2 ; port DOUT2_FMC_N
DOUT2_FMC_P: C88.2 ; port DOUT2_FMC_P
DOUT3_ADC_N: C93.1 U1.61(DOUT3M)
DOUT3_ADC_P: C90.1 U1.60(DOUT3P)
DOUT3_FMC_N: C93.2 ; port DOUT3_FMC_N
DOUT3_FMC_P: C90.2 ; port DOUT3_FMC_P
DOUT4_ADC_N: C95.1 U1.44(DOUT4M)
DOUT4_ADC_P: C94.1 U1.45(DOUT4P)
DOUT4_FMC_N: C95.2 ; port DOUT4_FMC_N
DOUT4_FMC_P: C94.2 ; port DOUT4_FMC_P
DOUT5_ADC_N: C97.1 U1.47(DOUT5M)
DOUT5_ADC_P: C96.1 U1.48(DOUT5P)
DOUT5_FMC_N: C97.2 ; port DOUT5_FMC_N
DOUT5_FMC_P: C96.2 ; port DOUT5_FMC_P
DOUT6_ADC_N: C100.1 U1.49(DOUT6M)
DOUT6_ADC_P: C98.1 U1.50(DOUT6P)
DOUT6_FMC_N: C100.2 ; port DOUT6_FMC_N
DOUT6_FMC_P: C98.2 ; port DOUT6_FMC_P
DOUT7_ADC_N: C104.1 U1.52(DOUT7M)
DOUT7_ADC_P: C102.1 U1.53(DOUT7P)
DOUT7_FMC_N: C104.2 ; port DOUT7_FMC_N
DOUT7_FMC_P: C102.2 ; port DOUT7_FMC_P
EXTCLK: C103.1 J4.1
GPIO1_ADC: U1.39(GPIO1) ; port GPIO1_ADC
GPIO2_ADC: U1.38(GPIO2) ; port GPIO2_ADC
INA1_ADC_N: U1.15(INA1M) ; port INA1_ADC_N
INA1_ADC_P: U1.14(INA1P) ; port INA1_ADC_P
INA2_ADC_N: U1.19(INA2M) ; port INA2_ADC_N
INA2_ADC_P: U1.18(INA2P) ; port INA2_ADC_P
INB1_ADC_N: U1.34(INB1M) ; port INB1_ADC_N
INB1_ADC_P: U1.35(INB1P) ; port INB1_ADC_P
INB2_ADC_N: U1.30(INB2M) ; port INB2_ADC_N
INB2_ADC_P: U1.31(INB2P) ; port INB2_ADC_P
RSTb_ADC: R24.2 U27.1(A) ; port RSTb_ADC
RSTb_MANUAL: R25.2 SW3.2 U27.2(B)
SCLK_ADC: U1.55(SCLK) ; port SCLK_ADC
SDIO_ADC: U1.56(SDIO) ; port SDIO_ADC
SEN_ADC: U1.57(SEN) ; port SEN_ADC
SPISEL_ADC: U1.10(SPISEL) ; port SPISEL_ADC
VCM: C91.2 C92.2 U1.26(VCM)
NetC44_2: C44.2 U11.5(CT)
NetC101_1: C101.1 R132.2
NetC101_2: C101.2 T3.6(Primary_Dot)
NetC103_2: C103.2 R134.1
NetR28_2: R28.2 R29.2 R133.2 U1.11(~{RESET})
NetR29_1: R29.1 U11.1(~{RESET})
NetR132_1: R132.1 R134.2 R135.1
NetR133_1: R133.1 U11.4(~{MR}) U27.4(Y)

Not connected (* = marked no-connect by the designer): U27 5(NC)*

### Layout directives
differential pair; net class SERDES_DP: DOUT0_ADC_N, DOUT0_ADC_P, DOUT1_ADC_N, DOUT1_ADC_P, DOUT2_ADC_N, DOUT2_ADC_P, DOUT3_ADC_N, DOUT3_ADC_P, DOUT4_ADC_N, DOUT4_ADC_P, DOUT5_ADC_N, DOUT5_ADC_P, DOUT6_ADC_N, DOUT6_ADC_P, DOUT7_ADC_N, DOUT7_ADC_P
differential pair: (no net found under the mark), CLK_ADC_N, CLK_ADC_P
net class Clock Power Divider: (no net found under the mark)

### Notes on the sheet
- (near R133) Note:
  Hardware power on reset (POR)
  AVDD18 supply is used as it is last of sequencing

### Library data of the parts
C44 = capcc01294: CAP CER 0.1UF 25V X5R 0201; Manufacturer: TDK Corporation; CompType: Capacitor Ceramic; Tolerance: ±10%; SizeX_mm: 0.6; SizeY_mm: 0.3; SizeZ_mm: 0.33
C84-C90 C93-C98 C100-C104 C106 C153 = 0201RFCaps0693: as C69 on sheet DC142D_ADC32RF55_ADC_Input_RevA1
C91 = capcc09406: CAP CER 10UF 10V X5R 0402; Manufacturer: KYOCERA AVX; CompType: Capacitor Ceramic; Tolerance: ±20%; SizeX_mm: 1; SizeY_mm: 0.5; SizeZ_mm: 0.7
C92 = capcc01294: as C71 on sheet DC142D_ADC32RF55_ADC_Input_RevA1
J4 = 132134-15: as J5 on sheet DC142D_ADC32RF55_ADC_Input_RevA1
R13 = CMP-0028070-1: RES, 100, 1%, 0.05 W, 0201; Manufacturer: Yageo America; Power_W: 50mW; TempCo: 200 ppm/C; Value_Code: 100R; U/M: EA; Value: 100; EIA_Code: E96; SizeX_mm: 0.6; SizeY_mm: 0.3; SizeZ_mm: 0.26; Value2: 0.05W; SizeArea_mm2: 0.18; AEC Qualified: N; VDC_V: 25V; AEC Category: Q200
R24 R25 R28 = RSMD020100762: as R40-R44 on sheet DC142D_ADC32RF55_MUX_RevA1
R29 R133 = RSMD020101699: as R73 on sheet DC142D_ADC32RF55_MUX_RevA1
R74 = RSMD020100289: as R45 on sheet DC142D_ADC32RF55_MUX_RevA1
R132 R134 R135 = RSMD020100063: RES SMD 16 OHM 1% 1/20W 0201; Manufacturer: Panasonic Electronic Components; CompType: Resistor SMD; Power (Watts): 0.05W, 1/20W; Temperature Coefficient: ±200ppm/°C
SW3 = cmp00291: SWITCH TACTILE SPST-NO 0.05A 12V; Manufacturer: Würth Elektronik; CompType: Push Button; SizeX_mm: 3; SizeY_mm: 3.5
T3 = TCM2-33WX+: as T1 on sheet DC142D_ADC32RF55_ADC_Input_RevA1
U1 = ADC32RF55RTD: Dual channel 14-bit 3.0 GSPS RF sampling data converter, RTD0064L (VQFN-64); Alternate Manufacturer: Texas Instruments; SizeX_mm: 9; CompType: IC; SizeAreaWB_mm2: 121; SizeZ_mm: 0.9; AEC Category: Q200; SizeArea_mm2: 81; AEC Qualified: N
U11 = TPS3840DL16DBV: Open Drain, 1.6V threshold, Nano Power, Wide VIN Voltage Detector with Programmable Delay; Manufacturer: Texas Instruments
U27 = cmp00518: Low-Power Single 2-Input Positive-AND Gate; PartNumber: SN74AUP1G08DRYR; Manufacturer: Texas Instruments

## Sheet DC142D_ADC32RF55_ADC_Power_RevA1.SchDoc: ADC EVM Power
size 431 x 279 mm; Date: Not shown in title block; ApprovedBy: Not shown in title block; CheckedBy: Not shown in title block; Author: Not shown in title block; CompanyName: Not shown in title block; DrawnBy: CW; Engineer: Not shown in title block; Organization: Not shown in title block; Address1: Not shown in title block; Address2: Not shown in title block; Address3: Not shown in title block; Address4: Not shown in title block; DocumentNumber: 4; Revision: Use project parameter SCH_Rev; SheetNumber: 9; SheetTotal: 13; PageSetup: Record=PageOptions¦CenterHorizontal=True¦CenterVertical=True¦PrintScale=1.00¦XCorrection=1.00¦YCorrection=1.00¦PrintKind=0¦BorderSize=5000000¦LeftOffset=0¦BottomOffset=0¦Orientation=2¦PaperLength=1000¦PaperWidth=1000¦Scale=100¦PaperSource=15¦PrintQuality=600¦MediaType=1¦DitherType=10¦PaperKind=Letter¦PrintScaleMode=1
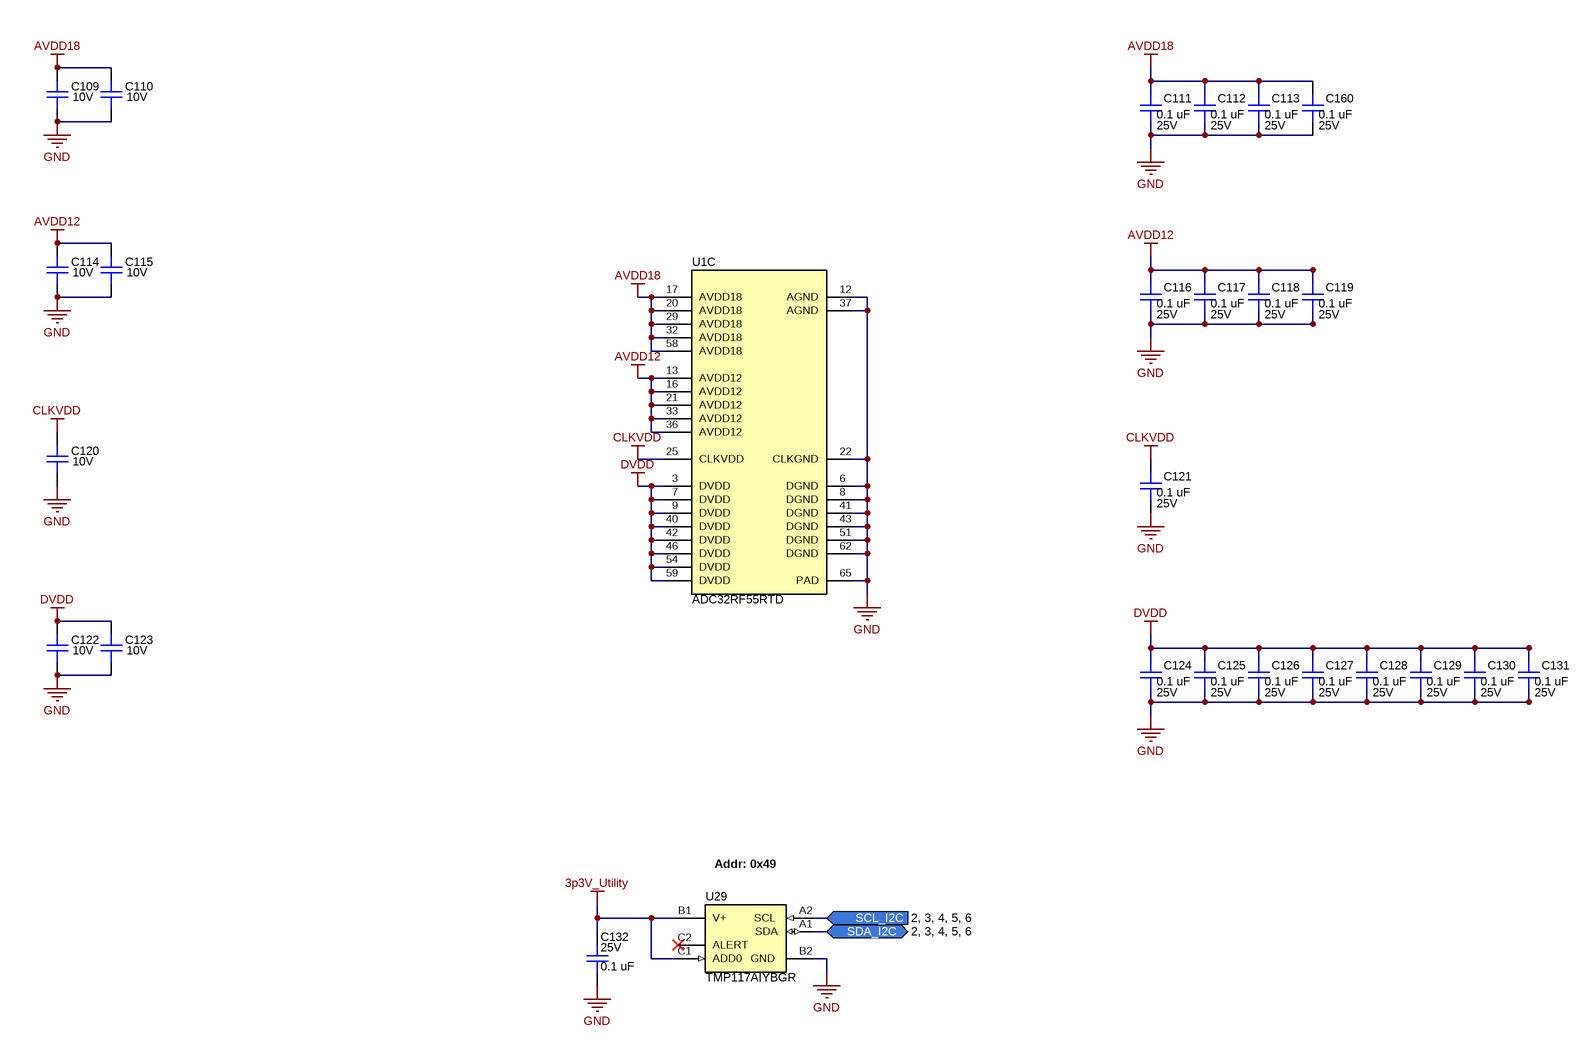
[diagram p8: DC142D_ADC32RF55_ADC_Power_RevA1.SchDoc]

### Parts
C109  Voltage - Rated: 10V  [0402L_cap]  (hidden comment: 0402ZD106MAT2A)
C110  Voltage - Rated: 10V  [0402L_cap]  (hidden comment: 0402ZD106MAT2A)
C111  value 0.1 uF  Voltage - Rated: 25V  [0201_cap]  (hidden comment: C0603X5R1E104K030BB)
C112  value 0.1 uF  Voltage - Rated: 25V  [0201_cap]  (hidden comment: C0603X5R1E104K030BB)
C113  value 0.1 uF  Voltage - Rated: 25V  [0201_cap]  (hidden comment: C0603X5R1E104K030BB)
C114  Voltage - Rated: 10V  [0402L_cap]  (hidden comment: 0402ZD106MAT2A)
C115  Voltage - Rated: 10V  [0402L_cap]  (hidden comment: 0402ZD106MAT2A)
C116  value 0.1 uF  Voltage - Rated: 25V  [0201_cap]  (hidden comment: C0603X5R1E104K030BB)
C117  value 0.1 uF  Voltage - Rated: 25V  [0201_cap]  (hidden comment: C0603X5R1E104K030BB)
C118  value 0.1 uF  Voltage - Rated: 25V  [0201_cap]  (hidden comment: C0603X5R1E104K030BB)
C119  value 0.1 uF  Voltage - Rated: 25V  [0201_cap]  (hidden comment: C0603X5R1E104K030BB)
C120  Voltage - Rated: 10V  [0402L_cap]  (hidden comment: 0402ZD106MAT2A)
C121  value 0.1 uF  Voltage - Rated: 25V  [0201_cap]  (hidden comment: C0603X5R1E104K030BB)
C122  Voltage - Rated: 10V  [0402L_cap]  (hidden comment: 0402ZD106MAT2A)
C123  Voltage - Rated: 10V  [0402L_cap]  (hidden comment: 0402ZD106MAT2A)
C124  value 0.1 uF  Voltage - Rated: 25V  [0201_cap]  (hidden comment: C0603X5R1E104K030BB)
C125  value 0.1 uF  Voltage - Rated: 25V  [0201_cap]  (hidden comment: C0603X5R1E104K030BB)
C126  value 0.1 uF  Voltage - Rated: 25V  [0201_cap]  (hidden comment: C0603X5R1E104K030BB)
C127  value 0.1 uF  Voltage - Rated: 25V  [0201_cap]  (hidden comment: C0603X5R1E104K030BB)
C128  value 0.1 uF  Voltage - Rated: 25V  [0201_cap]  (hidden comment: C0603X5R1E104K030BB)
C129  value 0.1 uF  Voltage - Rated: 25V  [0201_cap]  (hidden comment: C0603X5R1E104K030BB)
C130  value 0.1 uF  Voltage - Rated: 25V  [0201_cap]  (hidden comment: C0603X5R1E104K030BB)
C131  value 0.1 uF  Voltage - Rated: 25V  [0201_cap]  (hidden comment: C0603X5R1E104K030BB)
C132  value 0.1 uF  Voltage - Rated: 25V  [0201_cap]  (hidden comment: C0603X5R1E104K030BB)
C160  value 0.1 uF  Voltage - Rated: 25V  [0201_cap]  (hidden comment: C0603X5R1E104K030BB)
U1  ADC32RF55RTD  [RTD0064L]  (part C of 3)
U29  TMP117AIYBGR  [YBG0006AJAP]

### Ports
SCL_I2C (in, see 2, 3, 4, 5, 6), SDA_I2C (bidir, see 2, 3, 4, 5, 6)

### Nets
3p3V_Utility: C132.2 U29.B1(V+) U29.C1(ADD0)
AVDD12: C114.2 C115.2 C116.2 C117.2 C118.2 C119.2 U1.13(AVDD12) U1.16(AVDD12) U1.21(AVDD12) U1.33(AVDD12) U1.36(AVDD12)
AVDD18: C109.2 C110.2 C111.2 C112.2 C113.2 C160.2 U1.17(AVDD18) U1.20(AVDD18) U1.29(AVDD18) U1.32(AVDD18) U1.58(AVDD18)
CLKVDD: C120.2 C121.2 U1.25(CLKVDD)
DVDD: C122.2 C123.2 C124.2 C125.2 C126.2 C127.2 C128.2 C129.2 C130.2 C131.2 U1.3(DVDD) U1.7(DVDD) U1.9(DVDD) U1.40(DVDD) U1.42(DVDD) U1.46(DVDD) U1.54(DVDD) U1.59(DVDD)
GND: C109.1 C110.1 C111.1 C112.1 C113.1 C114.1 C115.1 C116.1 C117.1 C118.1 C119.1 C120.1 C121.1 C122.1 C123.1 C124.1 C125.1 C126.1 C127.1 C128.1 C129.1 C130.1 C131.1 C132.1 C160.1 U1.6(DGND) U1.8(DGND) U1.12(AGND) U1.22(CLKGND) U1.37(AGND) U1.41(DGND) U1.43(DGND) U1.51(DGND) U1.62(DGND) U1.65(PAD) U29.B2(GND)
SCL_I2C: U29.A2(SCL) ; port SCL_I2C
SDA_I2C: U29.A1(SDA) ; port SDA_I2C

Not connected (* = marked no-connect by the designer): U29 C2(ALERT)*

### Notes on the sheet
- (near U29) Addr: 0x49

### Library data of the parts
C109 C110 C114 C115 C120 C122 C123 = capcc09406: CAP CER 10UF 10V X5R 0402; Manufacturer: KYOCERA AVX; SizeZ_mm: 0.7; SizeX_mm: 1; SizeY_mm: 0.5; CompType: Capacitor Ceramic; Tolerance: ±20%
C111-C113 C116-C119 C121 C124-C132 C160 = capcc01294: as C71 on sheet DC142D_ADC32RF55_ADC_Input_RevA1
U1 = ADC32RF55RTD: as U1 on sheet DC142D_ADC32RF55_ADC_Dig_RevA1
U29 = cmp00348: ±0.1°C accurate digital temperature sensor with integrated NV memory, YBG0006AJAP (DSBGA-6); Manufacturer: Texas Instruments; CompType: Temp Sensor

## Sheet DC142D_ADC32RF55_LMK_RevA1.SchDoc: LMK04832 Clock Fanout
size 431 x 279 mm; Date: Not shown in title block; ApprovedBy: Not shown in title block; CheckedBy: Not shown in title block; Author: Not shown in title block; CompanyName: Not shown in title block; DrawnBy: CW; Engineer: Not shown in title block; Organization: Not shown in title block; Address1: Not shown in title block; Address2: Not shown in title block; Address3: Not shown in title block; Address4: Not shown in title block; DocumentNumber: 9; Revision: Use project parameter SCH_Rev; SheetNumber: 10; SheetTotal: 13; PageSetup: Record=PageOptions¦CenterHorizontal=True¦CenterVertical=True¦PrintScale=1.00¦XCorrection=1.00¦YCorrection=1.00¦PrintKind=0¦BorderSize=5000000¦LeftOffset=0¦BottomOffset=0¦Orientation=2¦PaperLength=1000¦PaperWidth=1000¦Scale=100¦PaperSource=15¦PrintQuality=600¦MediaType=1¦DitherType=10¦PaperKind=Letter¦PrintScaleMode=1
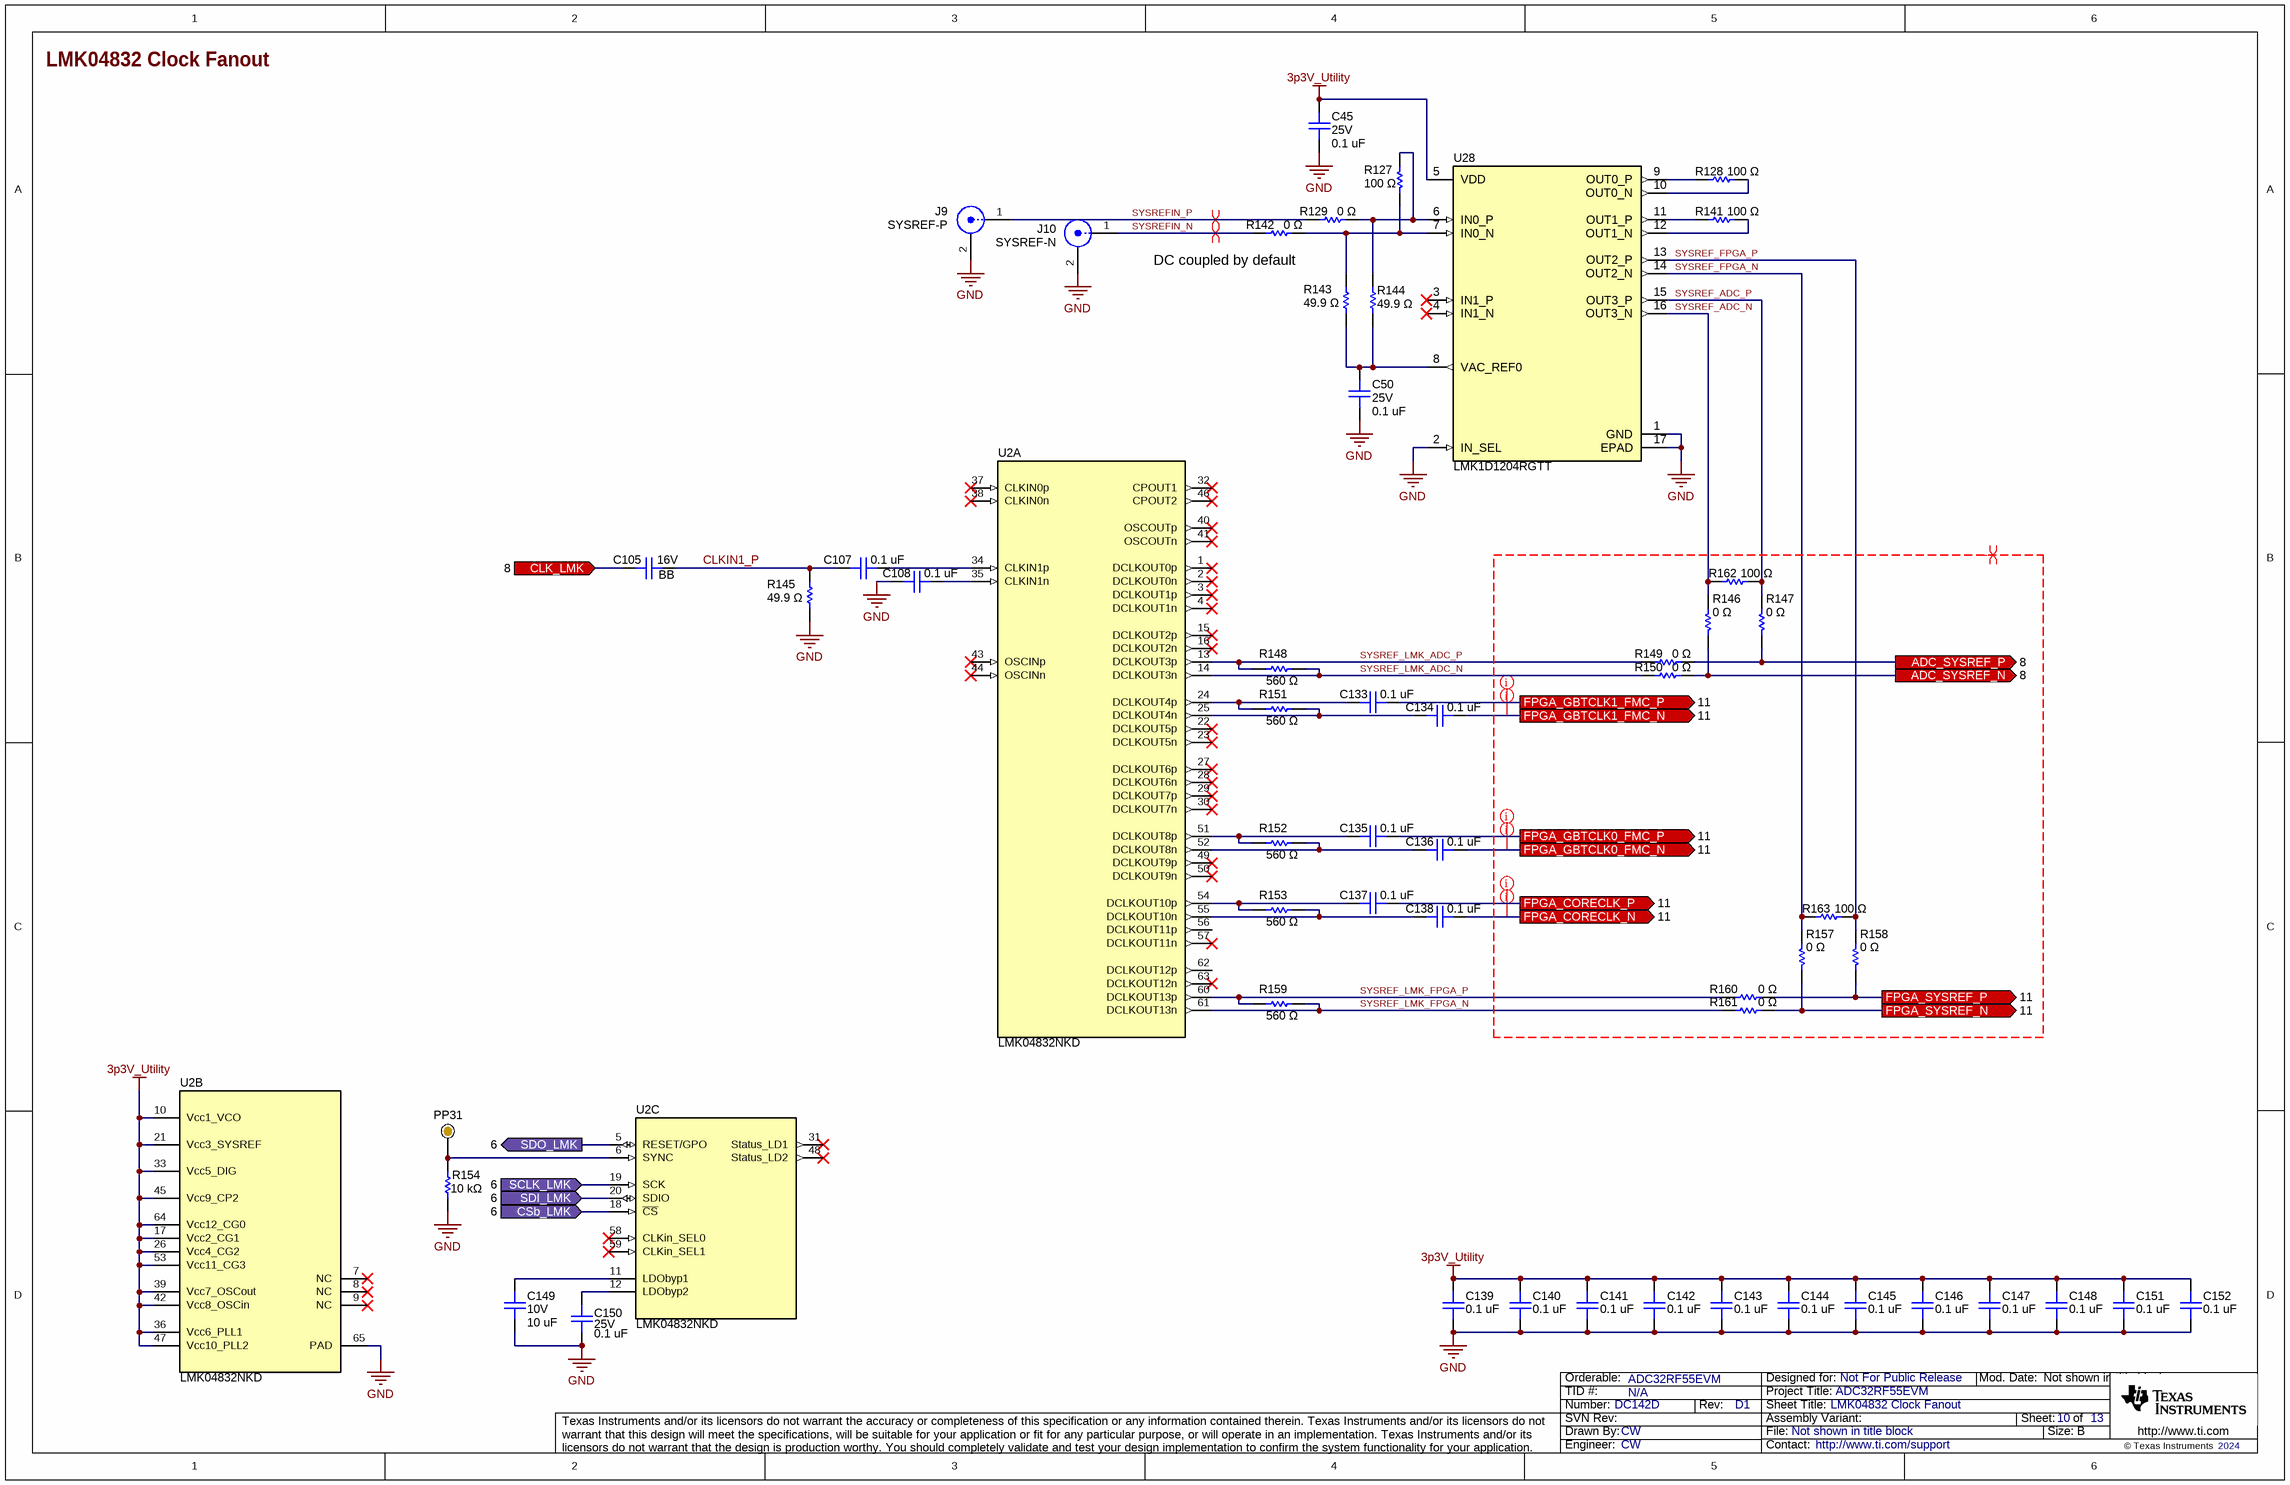
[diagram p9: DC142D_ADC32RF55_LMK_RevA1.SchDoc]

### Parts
C45  value 0.1 uF  Voltage - Rated: 25V  [0201_cap]  (hidden comment: C0603X5R1E104K030BB)
C50  value 0.1 uF  Voltage - Rated: 25V  [0201_cap]  (hidden comment: C0603X5R1E104K030BB)
C105  Voltage - Rated: 16V  Text: BB  [0201_cap]  (hidden comment: 0201BB104KW160)
C107  value 0.1 uF  [0201_cap]  (hidden comment: C0603X5R1E104K030BB)
C108  value 0.1 uF  [0201_cap]  (hidden comment: C0603X5R1E104K030BB)
C133  value 0.1 uF  [0201_cap]  (hidden comment: 0201BB104KW160)
C134  value 0.1 uF  [0201_cap]  (hidden comment: 0201BB104KW160)
C135  value 0.1 uF  [0201_cap]  (hidden comment: 0201BB104KW160)
C136  value 0.1 uF  [0201_cap]  (hidden comment: 0201BB104KW160)
C137  value 0.1 uF  [0201_cap]  (hidden comment: 0201BB104KW160)
C138  value 0.1 uF  [0201_cap]  (hidden comment: 0201BB104KW160)
C139  value 0.1 uF  [0201_cap]  (hidden comment: C0603X5R1E104K030BB)
C140  value 0.1 uF  [0201_cap]  (hidden comment: C0603X5R1E104K030BB)
C141  value 0.1 uF  [0201_cap]  (hidden comment: C0603X5R1E104K030BB)
C142  value 0.1 uF  [0201_cap]  (hidden comment: C0603X5R1E104K030BB)
C143  value 0.1 uF  [0201_cap]  (hidden comment: C0603X5R1E104K030BB)
C144  value 0.1 uF  [0201_cap]  (hidden comment: C0603X5R1E104K030BB)
C145  value 0.1 uF  [0201_cap]  (hidden comment: C0603X5R1E104K030BB)
C146  value 0.1 uF  [0201_cap]  (hidden comment: C0603X5R1E104K030BB)
C147  value 0.1 uF  [0201_cap]  (hidden comment: C0603X5R1E104K030BB)
C148  value 0.1 uF  [0201_cap]  (hidden comment: C0603X5R1E104K030BB)
C149  value 10 uF  Voltage - Rated: 10V  [0402L_cap]  (hidden comment: 0402ZD106MAT2A)
C150  value 0.1 uF  Voltage - Rated: 25V  [0201_cap]  (hidden comment: C0603X5R1E104K030BB)
C151  value 0.1 uF  [0201_cap]  (hidden comment: C0603X5R1E104K030BB)
C152  value 0.1 uF  [0201_cap]  (hidden comment: C0603X5R1E104K030BB)
J9  Text1: SYSREF-P  [Molex_0853050232]  (hidden comment: 0853050232)
J10  Text1: SYSREF-N  [Molex_0853050232]  (hidden comment: 0853050232)
PP31  Probe Point  [ProbePoint_TH_40mil]  (value not drawn)  (no BOM)
R127  value 100 Ω  [0201]  (hidden comment: ERJ-1GNF1000C)
R128  value 100 Ω  [0201]  (hidden comment: ERJ-1GNF1000C)
R129  value 0 Ω  [0201]  (hidden comment: ERJ-1GN0R00C)
R141  value 100 Ω  [0201]  (hidden comment: ERJ-1GNF1000C)
R142  value 0 Ω  [0201]  (hidden comment: ERJ-1GN0R00C)
R143  value 49.9 Ω  [0201]  (hidden comment: ERJ-1GNF49R9C)
R144  value 49.9 Ω  [0201]  (hidden comment: ERJ-1GNF49R9C)
R145  value 49.9 Ω  [0201]  (hidden comment: ERJ-1GNF49R9C)
R146  value 0 Ω  [0201]  (hidden comment: ERJ-1GN0R00C)
R147  value 0 Ω  [0201]  (hidden comment: ERJ-1GN0R00C)
R148  value 560 Ω  [0201]  (hidden comment: ERJ-1GNF5600C)
R149  value 0 Ω  [0201]  (hidden comment: ERJ-1GN0R00C)
R150  value 0 Ω  [0201]  (hidden comment: ERJ-1GN0R00C)
R151  value 560 Ω  [0201]  (hidden comment: ERJ-1GNF5600C)
R152  value 560 Ω  [0201]  (hidden comment: ERJ-1GNF5600C)
R153  value 560 Ω  [0201]  (hidden comment: ERJ-1GNF5600C)
R154  value 10 kΩ  [0201]  (hidden comment: ERJ-1GNF1002C)
R157  value 0 Ω  [0201]  (hidden comment: ERJ-1GN0R00C)
R158  value 0 Ω  [0201]  (hidden comment: ERJ-1GN0R00C)
R159  value 560 Ω  [0201]  (hidden comment: ERJ-1GNF5600C)
R160  value 0 Ω  [0201]  (hidden comment: ERJ-1GN0R00C)
R161  value 0 Ω  [0201]  (hidden comment: ERJ-1GN0R00C)
R162  value 100 Ω  [0201]  (hidden comment: ERJ-1GNF1000C)
R163  value 100 Ω  [0201]  (hidden comment: ERJ-1GNF1000C)
U2  LMK04832NKD  [NKD0064A]  (parts A,B,C of 3)
U28  PartNumber: LMK1D1204RGTT  [RGT0016C]  (hidden comment: LMK1D1204)

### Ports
ADC_SYSREF_N (out, see 8), ADC_SYSREF_P (out, see 8), CLK_LMK (in, see 8), CSb_LMK (in, see 6), FPGA_CORECLK_N (out, see 11), FPGA_CORECLK_P (out, see 11), FPGA_GBTCLK0_FMC_N (out, see 11), FPGA_GBTCLK0_FMC_P (out, see 11), FPGA_GBTCLK1_FMC_N (out, see 11), FPGA_GBTCLK1_FMC_P (out, see 11), FPGA_SYSREF_N (out, see 11), FPGA_SYSREF_P (out, see 11), SCLK_LMK (in, see 6), SDI_LMK (in, see 6), SDO_LMK (out, see 6)

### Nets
3p3V_Utility: C45.2 C139.1 C140.1 C141.1 C142.1 C143.1 C144.1 C145.1 C146.1 C147.1 C148.1 C151.1 C152.1 U2.10(Vcc1_VCO) U2.17(Vcc2_CG1) U2.21(Vcc3_SYSREF) U2.26(Vcc4_CG2) U2.33(Vcc5_DIG) U2.36(Vcc6_PLL1) U2.39(Vcc7_OSCout) U2.42(Vcc8_OSCin) U2.45(Vcc9_CP2) U2.47(Vcc10_PLL2) U2.53(Vcc11_CG3) U2.64(Vcc12_CG0) U28.5(VDD)
GND: C45.1 C50.1 C108.1 C139.2 C140.2 C141.2 C142.2 C143.2 C144.2 C145.2 C146.2 C147.2 C148.2 C149.1 C150.1 C151.2 C152.2 J9.2 J10.2 R145.1 R154.2 U2.65(PAD) U28.1(GND) U28.2(IN_SEL) U28.17(EPAD)
ADC_SYSREF_N: R146.1 R150.1 ; port ADC_SYSREF_N
ADC_SYSREF_P: R147.1 R149.1 ; port ADC_SYSREF_P
CLK_LMK: C105.1 ; port CLK_LMK
CLKIN1_P: C105.2 C107.2 R145.2
CSb_LMK: U2.18(~{CS}) ; port CSb_LMK
FPGA_CORECLK_N: C138.2 ; port FPGA_CORECLK_N
FPGA_CORECLK_P: C137.2 ; port FPGA_CORECLK_P
FPGA_GBTCLK0_FMC_N: C136.2 ; port FPGA_GBTCLK0_FMC_N
FPGA_GBTCLK0_FMC_P: C135.2 ; port FPGA_GBTCLK0_FMC_P
FPGA_GBTCLK1_FMC_N: C134.2 ; port FPGA_GBTCLK1_FMC_N
FPGA_GBTCLK1_FMC_P: C133.2 ; port FPGA_GBTCLK1_FMC_P
FPGA_SYSREF_N: R157.1 R161.1 ; port FPGA_SYSREF_N
FPGA_SYSREF_P: R158.1 R160.1 ; port FPGA_SYSREF_P
SCLK_LMK: U2.19(SCK) ; port SCLK_LMK
SDI_LMK: U2.20(SDIO) ; port SDI_LMK
SDO_LMK: U2.5(RESET/GPO) ; port SDO_LMK
SYSREF_ADC_N: R146.2 R162.1 U28.16(OUT3_N)
SYSREF_ADC_P: R147.2 R162.2 U28.15(OUT3_P)
SYSREF_FPGA_N: R157.2 R163.1 U28.14(OUT2_N)
SYSREF_FPGA_P: R158.2 R163.2 U28.13(OUT2_P)
SYSREF_LMK_ADC_N: R148.2 R150.2 U2.14(DCLKOUT3n)
SYSREF_LMK_ADC_P: R148.1 R149.2 U2.13(DCLKOUT3p)
SYSREF_LMK_FPGA_N: R159.2 R161.2 U2.61(DCLKOUT13n)
SYSREF_LMK_FPGA_P: R159.1 R160.2 U2.60(DCLKOUT13p)
SYSREFIN_N: J10.1 R142.2
SYSREFIN_P: J9.1 R129.2
NetC50_2: C50.2 R143.1 R144.1 U28.8(VAC_REF0)
NetC107_1: C107.1 U2.34(CLKIN1p)
NetC108_2: C108.2 U2.35(CLKIN1n)
NetC133_1: C133.1 R151.1 U2.24(DCLKOUT4p)
NetC134_1: C134.1 R151.2 U2.25(DCLKOUT4n)
NetC135_1: C135.1 R152.1 U2.51(DCLKOUT8p)
NetC136_1: C136.1 R152.2 U2.52(DCLKOUT8n)
NetC137_1: C137.1 R153.1 U2.54(DCLKOUT10p)
NetC138_1: C138.1 R153.2 U2.55(DCLKOUT10n)
NetC149_2: C149.2 U2.11(LDObyp1)
NetC150_2: C150.2 U2.12(LDObyp2)
NetPP31_1: PP31.1 R154.1 U2.6(SYNC)
NetR127_1: R127.1 R142.1 R143.2 U28.7(IN0_N)
NetR127_2: R127.2 R129.1 R144.2 U28.6(IN0_P)
NetR128_1: R128.1 U28.9(OUT0_P)
NetR128_2: R128.2 U28.10(OUT0_N)
NetR141_1: R141.1 U28.11(OUT1_P)
NetR141_2: R141.2 U28.12(OUT1_N)

Not connected (* = marked no-connect by the designer): U2 1(DCLKOUT0p)* 2(DCLKOUT0n)* 3(DCLKOUT1p)* 4(DCLKOUT1n)* 7(NC)* 8(NC)* 9(NC)* 15(DCLKOUT2p)* 16(DCLKOUT2n)* 22(DCLKOUT5p)* 23(DCLKOUT5n)* 27(DCLKOUT6p)* 28(DCLKOUT6n)* 29(DCLKOUT7p)* 30(DCLKOUT7n)* 31(Status_LD1)* 32(CPOUT1)* 37(CLKIN0p)* 38(CLKIN0n)* 40(OSCOUTp)* 41(OSCOUTn)* 43(OSCINp)* 44(OSCINn)* 46(CPOUT2)* 48(Status_LD2)* 49(DCLKOUT9p)* 50(DCLKOUT9n)* 56(DCLKOUT11p) 57(DCLKOUT11n)* 58(CLKin_SEL0)* 59(CLKin_SEL1)* 62(DCLKOUT12p) 63(DCLKOUT12n)*; U28 3(IN1_P)* 4(IN1_N)*

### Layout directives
net class FPGA MGT REFCLK: FPGA_GBTCLK0_FMC_N, FPGA_GBTCLK0_FMC_P, FPGA_GBTCLK1_FMC_N, FPGA_GBTCLK1_FMC_P
net class FPGA CORECLK: FPGA_CORECLK_N, FPGA_CORECLK_P
differential pair; net class SERDES_DP: (no net found under the mark)
differential pair: SYSREFIN_N, SYSREFIN_P

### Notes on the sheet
- (near R142) DC coupled by default

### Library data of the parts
C45 C50 = capcc01294: as C44 on sheet DC142D_ADC32RF55_ADC_Dig_RevA1
C105 = 0201RFCaps0693: as C69 on sheet DC142D_ADC32RF55_ADC_Input_RevA1
C107 C108 C139-C148 C150-C152 = capcc01294: as C71 on sheet DC142D_ADC32RF55_ADC_Input_RevA1
C133-C138 = 0201RFCaps0693: Broadband Capacitors; Manufacturer: Passive Plus; Alt PartNumber: GRM033C71C104ME14D; Alt Manufacturer: Murata Electronics; SizeZ_mm: 0.33; SizeY_mm: 0.3; CompType: Capactior RF; SizeX_mm: 0.58; Voltage - Rated: 16V; Tolerance: ±10%; Temperature Coefficient: C0G, NP0
C149 = capcc09406: as C91 on sheet DC142D_ADC32RF55_ADC_Dig_RevA1
J9 J10 = cmp00032: SMP Connector Plug, Male Pin 50Ohm Surface Mount Solder; Manufacturer: Molex; SymbolCreator: a0799628; Cert_UL: Y; ContactFinish: Gold; CompType: RF Connector; CT: False; Voltage_V: 335V
PP31 = cmp00025: Probe Point that can be used in lue of a test point; Text1: SYNC
R127 R128 R141 R162 R163 = RSMD020100289: as R45 on sheet DC142D_ADC32RF55_MUX_RevA1
R129 R142 R146 R147 R149 R150 R157 R158 R160 R161 = RSMD020101699: as R73 on sheet DC142D_ADC32RF55_MUX_RevA1
R143-R145 = RSMD020100177: RES SMD 49.9 OHM 1% 1/20W 0201; Manufacturer: Panasonic Electronic Components; CompType: Resistor SMD; Power (Watts): 0.05W, 1/20W; Temperature Coefficient: ±200ppm/°C
R148 R151-R153 R159 = RSMD020100132: RES SMD 560 OHM 1% 1/20W 0201; Manufacturer: Panasonic Electronic Components; CompType: Resistor SMD; Power (Watts): 0.05W, 1/20W; Temperature Coefficient: ±200ppm/°C
R154 = RSMD020100762: as R40-R44 on sheet DC142D_ADC32RF55_MUX_RevA1
U2 = LMK04832NKD: Ultra-low-noise, 3.2-GHz, 15-output, JESD204B clock jitter cleaner with dual loop; PartNumber: LMK04832NKDR; Manufacturer: Texas Instruments; Alt PartNumber: LMK04832NKDT; CompType: Clocking
U28 = cmp00271: Texas Instruments; Manufacturer_Part_Number: LMK1D1204RGTR; CompType: Buffer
